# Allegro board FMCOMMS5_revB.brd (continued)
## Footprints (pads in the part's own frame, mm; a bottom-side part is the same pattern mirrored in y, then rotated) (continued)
FL0603
  rect 0.787x0.711 smd: 1(0,-0.555) 3(0,0.555)
  rect 0.66x0.305 smd: 2(-0.955,0) 4(0.955,0)
L0402
  rect 0.699x0.635 smd: 1(-0.54,0) 2(0.54,0)
L0402-2
  rect 0.381x0.66 smd: 1(-0.419,0) 2(0.419,0)
L0805
  rect 1.295x1.473 smd: 1(-0.965,0) 2(0.965,0)
L0805-F
  rect 1.092x1.499 smd: 1(-1.046,0) 2(1.046,0)
L1210H67
  rect 1.245x2.007 smd: 1(-1.272,0) 2(1.272,0)
L7144A
  rect 0.686x1.016 smd: 1(-0.699,0) 2(0.699,0)
LED0603
  rect 0.965x0.762 smd: A(0.8,0) C(-0.8,0)
LSMSQ157H83
  rect 1.473x3.683 smd: 1(-1.232,0) 2(1.232,0)
LSMSQ189H123
  custom 0.435x0.435 smd: 1(-2.103,0) 2(2.103,0)
MSOP8
  rect 0.305x1.321 smd: 1(-0.975,-2.3) 2(-0.325,-2.3) 3(0.325,-2.3) 4(0.975,-2.3) 5(0.975,2.3) 6(0.325,2.3) 7(-0.325,2.3) 8(-0.975,2.3)
QFN8_3X3_PAD1_75X1_45
  oval 0.305x0.813 smd: 1(-0.75,-1.35) 2(-0.25,-1.35) 3(0.25,-1.35) 4(0.75,-1.35) 5(0.75,1.35) 6(0.25,1.35) 7(-0.25,1.35) 8(-0.75,1.35)
  rect 1.753x1.448 smd: PAD(0,0)
QFN8_3X3_PAD2_44X1_7
  oval 0.305x0.914 smd: 1(-0.75,-1.557) 2(-0.25,-1.557) 3(0.25,-1.557) 4(0.75,-1.557) 5(0.75,1.557) 6(0.25,1.557) 7(-0.25,1.557) 8(-0.75,1.557)
  rect 2.438x1.702 smd: PAD(0,0)
QFN16_3X3_PAD1_75X1_75
  oval 0.305x0.94 smd: 1(-0.75,-1.57) 2(-0.25,-1.57) 3(0.25,-1.57) 4(0.75,-1.57) 9(0.75,1.57) 10(0.25,1.57) 11(-0.25,1.57) 12(-0.75,1.57)
  oval 0.94x0.305 smd: 5(1.57,-0.75) 6(1.57,-0.25) 7(1.57,0.25) 8(1.57,0.75) 13(-1.57,0.75) 14(-1.57,0.25) 15(-1.57,-0.25) 16(-1.57,-0.75)
  rect 1.753x1.753 smd: PAD(0,0)
QFN16_4X4_PAD2_1X2_1
  oval 0.356x1.041 smd: 1(-0.975,-1.9) 2(-0.325,-1.9) 3(0.325,-1.9) 4(0.975,-1.9) 9(0.975,1.9) 10(0.325,1.9) 11(-0.325,1.9) 12(-0.975,1.9)
  oval 1.041x0.356 smd: 5(1.9,-0.975) 6(1.9,-0.325) 7(1.9,0.325) 8(1.9,0.975) 13(-1.9,0.975) 14(-1.9,0.325) 15(-1.9,-0.325) 16(-1.9,-0.975)
  rect 2.108x2.108 smd: PAD(0,0)
QFN16_4X4_PAD2_5X2_5
  oval 0.356x0.991 smd: 1(-0.975,-1.974) 2(-0.325,-1.974) 3(0.325,-1.974) 4(0.975,-1.974) 9(0.975,1.974) 10(0.325,1.974) 11(-0.325,1.974) 12(-0.975,1.974)
  oval 0.991x0.356 smd: 5(1.974,-0.975) 6(1.974,-0.325) 7(1.974,0.325) 8(1.974,0.975) 13(-1.974,0.975) 14(-1.974,0.325) 15(-1.974,-0.325) 16(-1.974,-0.975)
  rect 2.489x2.489 smd: PAD(0,0)
QFN20_4X4_PAD2_6X2_6
  oval 0.305x1.041 smd: 1(-1,-2.019) 2(-0.5,-2.019) 3(0,-2.019) 4(0.5,-2.019) 5(1,-2.019) 11(1,2.019) 12(0.5,2.019) 13(0,2.019) 14(-0.5,2.019) 15(-1,2.019)
  oval 1.041x0.305 smd: 6(2.019,-1) 7(2.019,-0.5) 8(2.019,0) 9(2.019,0.5) 10(2.019,1) 16(-2.019,1) 17(-2.019,0.5) 18(-2.019,0) 19(-2.019,-0.5) 20(-2.019,-1)
  rect 2.591x2.591 smd: PAD(0,0)
QFN24_4X4_PAD2_3X2_3
  oval 0.305x0.991 smd: 1(-1.25,-2) 2(-0.75,-2) 3(-0.25,-2) 4(0.25,-2) 5(0.75,-2) 6(1.25,-2) 13(1.25,2) 14(0.75,2) 15(0.25,2) 16(-0.25,2) 17(-0.75,2) 18(-1.25,2)
  oval 0.991x0.305 smd: 7(2,-1.25) 8(2,-0.75) 9(2,-0.25) 10(2,0.25) 11(2,0.75) 12(2,1.25) 19(-2,1.25) 20(-2,0.75) 21(-2,0.25) 22(-2,-0.25) 23(-2,-0.75) 24(-2,-1.25)
  rect 2.311x2.311 smd: PAD(0,0)
QFN32_5X5_PAD3_5X3_5
  oval 0.305x0.889 smd: 1(-1.75,-2.45) 2(-1.25,-2.45) 3(-0.75,-2.45) 4(-0.25,-2.45) 5(0.25,-2.45) 6(0.75,-2.45) 7(1.25,-2.45) 8(1.75,-2.45) 17(1.75,2.45) 18(1.25,2.45) 19(0.75,2.45) 20(0.25,2.45) 21(-0.25,2.45) 22(-0.75,2.45) 23(-1.25,2.45) 24(-1.75,2.45)
  oval 0.889x0.305 smd: 9(2.45,-1.75) 10(2.45,-1.25) 11(2.45,-0.75) 12(2.45,-0.25) 13(2.45,0.25) 14(2.45,0.75) 15(2.45,1.25) 16(2.45,1.75) 25(-2.45,1.75) 26(-2.45,1.25) 27(-2.45,0.75) 28(-2.45,0.25) 29(-2.45,-0.25) 30(-2.45,-0.75) 31(-2.45,-1.25) 32(-2.45,-1.75)
  rect 3.505x3.505 smd: PAD(0,0)
R0201
  rect 0.356x0.356 smd: 1(-0.305,0) 2(0.305,0)
R0402
  rect 0.889x0.813 smd: 1(-0.635,0) 2(0.635,0)
R0603
  rect 0.978x0.889 smd: 1(-0.819,0) 2(0.819,0)
R1206
  rect 1.6x1.6 smd: 1(-1.397,0) 2(1.397,0)
SO8NB-PAD3_1X2_41
  rect 0.635x1.524 smd: 1(-1.905,-2.667) 2(-0.635,-2.667) 3(0.635,-2.667) 4(1.905,-2.667) 5(1.905,2.667) 6(0.635,2.667) 7(-0.635,2.667) 8(-1.905,2.667)
  rect 3.099x2.413 smd: PAD(0,0)
SOT-89
  rect 0.991x1.499 smd: 1(-1.5,-2.224) 3(1.5,-2.224)
  rect 0.991x1.981 smd: 2(0,-1.983)
  rect 2.007x2.997 smd: 4(0,0.728)
TPC75D45
  round 1.905 smd: 1(0,0)
TPSM70X135
  rect 0.356x0.762 smd: 1(0,0)
TSML150W160H160
  rect 0.762x1.651 smd: 1(-1.27,1.587) 2(0,1.587) 3(1.27,1.587) 4(1.27,-1.587) 5(0,-1.587) 6(-1.27,-1.587)
TSSOP8
  rect 0.33x1.651 smd: 1(-0.975,-2.92) 2(-0.325,-2.92) 3(0.325,-2.92) 4(0.975,-2.92) 5(0.975,2.92) 6(0.325,2.92) 7(-0.325,2.92) 8(-0.975,2.92)
unnamed#2
  round 3.175 hole 2.667: 1(0,0)
XFMR2450BL15B050
  rect 0.356x0.991 smd: 1(-0.656,-0.895) 2(0,-0.895) 3(0.656,-0.895) 4(0.656,0.895) 5(0,0.895) 6(-0.656,0.895)
YSML126W98H47
  rect 1.397x1.194 smd: 1(-1.2,-0.95) 2(1.2,-0.95) 3(1.2,0.95) 4(-1.2,0.95)

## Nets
3.3VAUX: C310.1(N1) C311.2(N2) C312.1(N1) P401.D32(N32) P402.D32(N32) R401.2(N2) R402.2(N2) U303.8(VCC) U304.10(VDD) U304.16(VDRIVE) U304.17(PD_N/RST_N)
5V: C540.2(N2) C541.2(N2) C542.2(N2) E507.1(N1) E509.1(N1) R309.1(N1) TP306.1(N1) U502.2(VOUT)
12V: C530.2(N2) C531.2(N2) C532.2(N2) C533.2(N2) P401.C35(N35) P401.C37(N37) P402.C35(N35) P402.C37(N37) P501.3(N3) U501.1(VIN) U501.4(SYNC)
GND_POWER: C103.2(N2) C104.1(N1) C105.2(N2) C112.1(N1) C113.1(N1) C114.1(N1) C115.1(N1) C116.2(N2) C117.2(N2) C118.1(N1) C119.2(N2) C120.1(N1) C121.2(N2) C134.1(N1) C135.2(N2) C143.2(N2) C144.2(N2) C145.2(N2) C146.1(N1) C147.1(N1) C148.2(N2) C149.1(N1) C150.2(N2) C151.1(N1) C152.2(N2) C153.1(N1) C154.1(N1) C155.1(N1) C156.1(N1) C166.1(N1) C203.2(N2) C204.1(N1) C205.2(N2) C212.1(N1) C213.1(N1) C214.1(N1) C215.1(N1) C216.2(N2) C217.2(N2) C218.1(N1) C219.2(N2) C220.1(N1) C221.2(N2) C234.1(N1) C235.2(N2) C243.2(N2) C244.2(N2) C245.2(N2) C246.1(N1) C247.1(N1) C248.2(N2) C249.1(N1) C250.2(N2) C251.1(N1) C252.2(N2) C253.1(N1) C254.1(N1) C255.1(N1) C256.1(N1) C266.1(N1) C302.2(N2) C303.2(N2) C304.2(N2) C305.2(N2) C306.2(N2) C307.2(N2) C308.2(N2) C309.1(N1) C310.2(N2) C311.1(N1) C312.2(N2) C313.2(N2) C314.2(N2) C317.1(N1) C320.1(N1) C321.1(N1) C322.1(N1) C323.1(N1) C324.1(N1) C325.1(N1) C326.1(N1) C327.1(N1) C328.1(N1) C330.1(N1) C333.2(N2) C334.2(N2) C335.2(N2) C340.2(N2) C341.2(N2) C342.2(N2) C343.2(N2) C344.2(N2) C345.2(N2) C346.2(N2) C347.2(N2) C348.1(N1) C501.2(N2) C502.2(N2) C503.2(N2) C504.2(N2) C505.2(N2) C510.2(N2) C511.2(N2) C512.2(N2) C513.2(N2) C514.2(N2) C515.2(N2) C516.2(N2) C517.2(N2) C518.2(N2) C519.2(N2) C520.2(N2) C521.2(N2) C522.2(N2) C523.2(N2) C524.2(N2) C525.2(N2) C530.1(N1) C531.1(N1) C532.1(N1) C533.1(N1) C534.1(N1) C535.1(N1) C536.1(N1) C537.2(N2) C538.1(N1) C539.1(N1) C540.1(N1) C541.1(N1) C542.1(N1) C543.1(N1) C544.1(N1) C545.2(N2) C546.2(N2) C547.1(N1) C548.1(N1) C549.2(N2) C550.1(N1) C551.2(N2) C552.2(N2) C553.1(N1) C554.1(N1) C555.2(N2) C556.2(N2) C557.2(N2) C558.2(N2) C559.2(N2) C560.2(N2) C561.2(N2) C562.2(N2) C563.2(N2) C564.2(N2) C565.2(N2) C566.2(N2) C567.2(N2) C568.2(N2) C569.2(N2) C570.2(N2) C571.2(N2) C572.2(N2) C573.2(N2) C574.2(N2) C575.2(N2) C576.2(N2) C577.2(N2) C578.2(N2) C579.2(N2) C580.2(N2) C581.2(N2) C582.2(N2) C583.2(N2) C584.2(N2) C585.2(N2) C586.2(N2) C587.2(N2) C588.2(N2) C589.2(N2) C590.2(N2) C591.2(N2) C592.2(N2) C593.2(N2) C594.2(N2) C595.2(N2) C596.2(N2) C597.2(N2) C598.2(N2) C599.2(N2) C607.2(N2) C608.2(N2) C609.2(N2) C610.2(N2) C611.2(N2) C612.2(N2) C613.2(N2) C614.2(N2) C615.2(N2) C616.2(N2) C617.2(N2) C618.2(N2) C619.2(N2) C620.2(N2) C621.2(N2) C622.2(N2) C623.2(N2) C624.2(N2) C625.2(N2) C626.2(N2) C627.2(N2) C628.2(N2) C629.2(N2) C630.2(N2) C631.2(N2) C632.2(N2) C633.2(N2) C634.2(N2) C635.2(N2) C636.2(N2) C637.2(N2) C638.2(N2) C639.2(N2) C640.2(N2) C641.2(N2) C642.2(N2) C643.1(N1) C644.1(N1) C645.1(N1) C646.1(N1) C647.1(N1) C648.1(N1) C649.1(N1) C650.2(N2) C651.1(N1) C688.1(N1) DS301.C(N) FL100.1(GND1) FL100.3(GND2) FL101.1(GND1) FL101.3(GND2) FL102.1(GND1) FL102.3(GND2) FL103.1(GND1) FL103.3(GND2) FL200.1(GND1) FL200.3(GND2) FL201.1(GND1) FL201.3(GND2) FL202.1(GND1) FL202.3(GND2) FL203.1(GND1) FL203.3(GND2) J101.2(SH1) J101.3(SH2) J101.4(SH3) J101.5(SH4) J102.2(SH1) J102.3(SH2) J102.4(SH3) J102.5(SH4) J103.2(SH1) J103.3(SH2) J103.4(SH3) J103.5(SH4) J104.2(SH1) J104.3(SH2) J104.4(SH3) J104.5(SH4) J110.2(SH1) J110.3(SH2) J110.4(SH3) J110.5(SH4) J111.2(SH1) J111.3(SH2) J111.4(SH3) J111.5(SH4) J112.2(SH1) J112.3(SH2) J112.4(SH3) J112.5(SH4) J113.2(SH1) J113.3(SH2) J113.4(SH3) J113.5(SH4) J201.2(SH1) J201.3(SH2) J201.4(SH3) J201.5(SH4) J202.2(SH1) J202.3(SH2) J202.4(SH3) J202.5(SH4) J203.2(SH1) J203.3(SH2) J203.4(SH3) J203.5(SH4) J204.2(SH1) J204.3(SH2) J204.4(SH3) J204.5(SH4) J210.2(SH1) J210.3(SH2) J210.4(SH3) J210.5(SH4) J211.2(SH1) J211.3(SH2) J211.4(SH3) J211.5(SH4) J212.2(SH1) J212.3(SH2) J212.4(SH3) J212.5(SH4) J213.2(SH1) J213.3(SH2) J213.4(SH3) J213.5(SH4) J301.2(SH1) J301.3(SH2) J301.4(SH3) J301.5(SH4) J302.2(SH1) J302.3(SH2) J302.4(SH3) J302.5(SH4) P101.26(N26) P201.26(N26) P401.C1(N1) P401.C4(N4) P401.C5(N5) P401.C8(N8) P401.C9(N9) P401.C12(N12) P401.C13(N13) P401.C16(N16) P401.C17(N17) P401.C20(N20) P401.C21(N21) P401.C24(N24) P401.C25(N25) P401.C28(N28) P401.C29(N29) P401.C32(N32) P401.C33(N33) P401.C36(N36) P401.C38(N38) P401.C40(N40) P401.D2(N2) P401.D3(N3) P401.D6(N6) P401.D7(N7) P401.D10(N10) P401.D13(N13) P401.D16(N16) P401.D19(N19) P401.D22(N22) P401.D25(N25) P401.D28(N28) P401.D37(N37) P401.D39(N39) P401.G1(N1) P401.G4(N4) P401.G5(N5) P401.G8(N8) P401.G11(N11) P401.G14(N14) P401.G17(N17) P401.G20(N20) P401.G23(N23) P401.G26(N26) P401.G29(N29) P401.G32(N32) P401.G35(N35) P401.G38(N38) P401.G40(N40) P401.H2(N2) P401.H3(N3) P401.H6(N6) P401.H9(N9) P401.H12(N12) P401.H15(N15) P401.H18(N18) P401.H21(N21) P401.H24(N24) P401.H27(N27) P401.H30(N30) P401.H33(N33) P401.H36(N36) P401.H39(N39) P402.C1(N1) P402.C4(N4) P402.C5(N5) P402.C8(N8) P402.C9(N9) P402.C12(N12) P402.C13(N13) P402.C16(N16) P402.C17(N17) P402.C20(N20) P402.C21(N21) P402.C24(N24) P402.C25(N25) P402.C28(N28) P402.C29(N29) P402.C32(N32) P402.C33(N33) P402.C36(N36) P402.C38(N38) P402.C40(N40) P402.D2(N2) P402.D3(N3) P402.D6(N6) P402.D7(N7) P402.D10(N10) P402.D13(N13) P402.D16(N16) P402.D19(N19) P402.D22(N22) P402.D25(N25) P402.D28(N28) P402.D37(N37) P402.D39(N39) P402.G1(N1) P402.G4(N4) P402.G5(N5) P402.G8(N8) P402.G11(N11) P402.G14(N14) P402.G17(N17) P402.G20(N20) P402.G23(N23) P402.G26(N26) P402.G29(N29) P402.G32(N32) P402.G35(N35) P402.G38(N38) P402.G40(N40) P402.H2(N2) P402.H3(N3) P402.H6(N6) P402.H9(N9) P402.H12(N12) P402.H15(N15) P402.H18(N18) P402.H21(N21) P402.H24(N24) P402.H27(N27) P402.H30(N30) P402.H33(N33) P402.H36(N36) P402.H39(N39) P501.2(N2) R101.1(N1) R102.1(N1) R104.2(N2) R105.2(N2) R106.2(N2) R107.2(N2) R111.1(N1) R125.2(N2) R201.1(N1) R202.1(N1) R204.2(N2) R205.2(N2) R206.2(N2) R207.2(N2) R211.1(N1) R225.2(N2) R301.1(N1) R306.1(N1) R307.1(N1) R308.1(N1) R312.1(N1) R313.1(N1) R314.1(N1) R315.1(N1) R319.2(N2) R320.2(N2) R323.1(N1) R328.1(N1) R329.1(N1) R335.1(N1) R350.1(N1) R351.2(N2) R406.2(N2) R501.1(N1) R505.1(N1) R509.1(N1) R513.1(N1) R517.1(N1) R521.2(N2) T101.2(GND_DC_FEED_RFGND) T101.5(GND) T102.2(GND_DC_FEED_RFGND) T102.5(GND) T103.1(NC1) T103.2(PRI) T103.5(NC2) T104.1(NC1) T104.2(PRI) T104.5(NC2) T105.1(NC1) T105.2(PRI) T105.5(NC2) T106.1(NC1) T106.2(PRI) T106.5(NC2) T107.1(NC1) T107.2(PRI) T107.5(NC2) T108.1(NC1) T108.2(PRI) T108.5(NC2) T201.2(GND_DC_FEED_RFGND) T201.5(GND) T202.2(GND_DC_FEED_RFGND) T202.5(GND) T203.1(NC1) T203.2(PRI) T203.5(NC2) T204.1(NC1) T204.2(PRI) T204.5(NC2) T205.1(NC1) T205.2(PRI) T205.5(NC2) T206.1(NC1) T206.2(PRI) T206.5(NC2) T207.1(NC1) T207.2(PRI) T207.5(NC2) T208.1(NC1) T208.2(PRI) T208.5(NC2) U101.A4(VSSA26) U101.A6(VSSA01) U101.B1(VSSA02) U101.B2(VSSA03) U101.B12(VSSA04) U101.C1(RX2C_P) U101.C2(VSSA05) U101.C4(TEST/ENABLE) U101.C7(VSSA06) U101.C8(VSSA07) U101.C9(VSSA08) U101.C10(VSSA09) U101.C11(VSSA10) U101.C12(VSSA11) U101.D1(RX2C_N) U101.D12(VSSD01) U101.F3(VSSA12) U101.F7(VSSD02) U101.F9(VSSD03) U101.F11(VSSD04) U101.G12(VSSD05) U101.H2(VSSA13) U101.H3(VSSA14) U101.H6(VSSA28) U101.H7(VSSD06) U101.H10(VSSD07) U101.J2(VSSA15) U101.K2(VSSA16) U101.K12(VSSD08) U101.L2(VSSA17) U101.L3(VSSA18) U101.L7(VSSA19) U101.L8(VSSA20) U101.L9(VSSA21) U101.L10(VSSA22) U101.L11(VSSA23) U101.L12(VSSA24) U101.M4(VSSA27) U101.M6(VSSA25) U102.PAD U103.PAD U104.2(GND) U104.4(GND1) U105.2(GND) U105.4(GND1) U201.A4(VSSA26) U201.A6(VSSA01) U201.B1(VSSA02) U201.B2(VSSA03) U201.B12(VSSA04) U201.C1(RX2C_P) U201.C2(VSSA05) U201.C4(TEST/ENABLE) U201.C7(VSSA06) U201.C8(VSSA07) U201.C9(VSSA08) U201.C10(VSSA09) U201.C11(VSSA10) U201.C12(VSSA11) U201.D1(RX2C_N) U201.D12(VSSD01) U201.F3(VSSA12) U201.F7(VSSD02) U201.F9(VSSD03) U201.F11(VSSD04) U201.G12(VSSD05) U201.H2(VSSA13) U201.H3(VSSA14) U201.H6(VSSA28) U201.H7(VSSD06) U201.H10(VSSD07) U201.J2(VSSA15) U201.K2(VSSA16) U201.K12(VSSD08) U201.L2(VSSA17) U201.L3(VSSA18) U201.L7(VSSA19) U201.L8(VSSA20) U201.L9(VSSA21) U201.L10(VSSA22) U201.L11(VSSA23) U201.L12(VSSA24) U201.M4(VSSA27) U201.M6(VSSA25) U202.PAD U203.PAD U204.2(GND) U204.4(GND1) U205.2(GND) U205.4(GND1) U301.6(CTRL_B) U301.7(SLEEP) U301.PAD U302.8(CPGND) U302.9(AGND) U302.13(AGNDRF1) U302.15(AGNDRF2) U302.18(AGNDVCO1) U302.21(AGNDVCO2) U302.31(SDGND) U302.PAD U303.3(E2) U303.4(VSS) U303.7(WC_N) U304.6(GND1) U304.9(GND) U304.PAD U305.3(GND1) U305.6(GND2) U305.7(GND3) U306.3(GND1) U306.6(GND2) U306.7(GND3) U307.1(GND1) U307.4(GND2) U307.5(GND3) U307.8(GND4) U307.9(GND5) U307.12(GND6) U307.14(GND7) U307.PAD U501.2(FSEL) U501.8(PGND) U501.PAD(EPAD) U502.4(GND) U502.PAD(EP) U503.2(RT) U503.5(GND) U503.6(PGND_1) U503.7(PGND_2) U503.8(PGND_3) U503.PAD U504.6(GND) U504.PAD U505.6(GND) U505.PAD U506.6(GND) U506.PAD U507.6(GND) U507.PAD U508.4(GND) U508.PAD(EP) Y301.2(GND)
VDD_AMP_5V: C103.1(N1) C112.2(N2) C113.2(N2) C152.1(N1) C153.2(N2) C154.2(N2) C203.1(N1) C212.2(N2) C213.2(N2) C252.1(N1) C253.2(N2) C254.2(N2) C547.2(N2) C548.2(N2) E509.2(N2) L110.2(N2) L111.2(N2) L210.2(N2) L211.2(N2)
VDD_EXT_LO_3P3: C306.1(N1) C307.1(N1) C308.1(N1) C333.1(N1) C334.1(N1) C335.1(N1) C648.2(N2) C649.2(N2) C651.2(N2) C688.2(N2) R303.1(N1) R317.2(N2) R318.2(N2) U302.4(CE) U302.10(VRF) U302.16(AVDD_2) U302.27(DVDD) U307.13(VCC1) U307.15(VCC2) U307.16(VCC3) U508.2(VOUT)
VDD_INTERFACE_A: C610.1(N1) C611.1(N1) C612.1(N1) C613.1(N1) E512.2(N2) R103.1(N1) R403.1(N1) R407.1(N1) R507.2(N2) R511.2(N2) U101.H12(VDD_INTERFACE)
VDD_INTERFACE_B: C614.1(N1) C615.1(N1) C616.1(N1) C617.1(N1) E514.2(N2) R203.1(N1) R405.1(N1) R515.2(N2) R519.2(N2) U201.H12(VDD_INTERFACE)
VDD_LNA_3P3: C148.1(N1) C150.1(N1) C248.1(N1) C250.1(N1) C510.1(N1) C511.1(N1) C512.1(N1) C513.1(N1) E504.1(N1) R109.2(N2) R112.2(N2) R209.2(N2) R212.2(N2)
VDD_RF_SW: C340.1(N1) C341.1(N1) C342.1(N1) C343.1(N1) C344.1(N1) C345.1(N1) C638.1(N1) C639.1(N1) C640.1(N1) C641.1(N1) E1.2(N2) U305.1(VDD) U306.1(VDD)
VDD_VCO_5V: C309.2(N2) C317.2(N2) C320.2(N2) C323.2(N2) C543.2(N2) C544.2(N2) E507.2(N2) U302.6(VP) U302.17(VVCO) U302.19(VREGVCO)
VDDA_GPO_A: C518.1(N1) C519.1(N1) C520.1(N1) C521.1(N1) E501.2(N2) U101.B8(VDDA_GPO)
VDDA_GPO_B: C522.1(N1) C523.1(N1) C524.1(N1) C525.1(N1) E503.2(N2) U201.B8(VDDA_GPO)
1P3_DIG_A: C118.2(N2) C119.1(N1) C120.2(N2) C121.1(N1) C134.2(N2) C135.1(N1) C584.1(N1) C585.1(N1) C586.1(N1) C587.1(N1) C588.1(N1) C589.1(N1) C590.1(N1) C591.1(N1) C592.1(N1) C593.1(N1) L101.1(N1) L102.1(N1) L103.1(N1) L104.1(N1) L105.1(N1) L107.1(N1) R325.1(N1) R514.2(N2) U101.D2(VDDA1P3_RX_RF) U101.D3(VDDA1P3_RX_TX) U101.E3(VDDA1P3_TX_LO_BUFFER) U101.F12(VDDD1P3_DIG) U101.K4(VDDA1P3_BB)
1P3_DIG_B: C218.2(N2) C219.1(N1) C220.2(N2) C221.1(N1) C234.2(N2) C235.1(N1) C628.1(N1) C629.1(N1) C630.1(N1) C631.1(N1) C632.1(N1) C633.1(N1) C634.1(N1) C635.1(N1) C636.1(N1) C637.1(N1) L201.1(N1) L202.1(N1) L203.1(N1) L204.1(N1) L205.1(N1) L207.1(N1) R327.1(N1) R522.1(N1) U201.D2(VDDA1P3_RX_RF) U201.D3(VDDA1P3_RX_TX) U201.E3(VDDA1P3_TX_LO_BUFFER) U201.F12(VDDD1P3_DIG) U201.K4(VDDA1P3_BB)
1P3_RF_A: C568.1(N1) C569.1(N1) C570.1(N1) C571.1(N1) C572.1(N1) C573.1(N1) C574.1(N1) C575.1(N1) R326.1(N1) R510.2(N2) U101.B9(VDDA1P3_TX_LO) U101.B10(VDDA1P3_TX_VCO_LDO) U101.E2(VDDA1P3_RX_LO) U101.F2(VDDA1P3_RX_VCO_LDO) U101.J3(VDDA1P3_RX_SYNTH) U101.K3(VDDA1P3_TX_SYNTH)
1P3_RF_B: C515.1(N1) C516.1(N1) C517.1(N1) C545.1(N1) C546.1(N1) C607.1(N1) C608.1(N1) C609.1(N1) R310.1(N1) R518.2(N2) TP307.1(N1) U201.B9(VDDA1P3_TX_LO) U201.B10(VDDA1P3_TX_VCO_LDO) U201.E2(VDDA1P3_RX_LO) U201.F2(VDDA1P3_RX_VCO_LDO) U201.J3(VDDA1P3_RX_SYNTH) U201.K3(VDDA1P3_TX_SYNTH)
1P3_TX2A_A: U101.A9(TX2B_N) U101.A10(TX2B_P)
1P3_TX2A_B: U201.A9(TX2B_N) U201.A10(TX2B_P)
1P8_CLK: C303.1(N1) C304.1(N1) C305.1(N1) C346.1(N1) C347.1(N1) C557.1(N1) C558.1(N1) C559.1(N1) E511.2(N2) U301.4(VS1) U301.5(CTRL_A) U301.10(VS2) U301.13(VS3) U301.16(VS4) U301.19(VS5) U301.22(VS6) Y301.1(E/D) Y301.4(VDD)
1P8V: C553.2(N2) C554.2(N2) C555.1(N1) C556.1(N1) C560.1(N1) C576.1(N1) C594.1(N1) C620.1(N1) E510.2(N2) E511.1(N1) E513.1(N1) R302.2(N2) R305.1(N1) R506.2(N2) TP303.1(N1) U504.1(VIN1) U504.2(VIN2) U504.3(VIN3) U504.15(VIN4) U504.16(VIN5) U505.1(VIN1) U505.2(VIN2) U505.3(VIN3) U505.15(VIN4) U505.16(VIN5) U506.1(VIN1) U506.2(VIN2) U506.3(VIN3) U506.15(VIN4) U506.16(VIN5) U507.1(VIN1) U507.2(VIN2) U507.3(VIN3) U507.15(VIN4) U507.16(VIN5)
3P3V: C501.1(N1) C502.1(N1) L501.1(N1) P401.C39(N39) P401.D36(N36) P401.D38(N38) P401.D40(N40) P402.C39(N39) P402.D36(N36) P402.D38(N38) P402.D40(N40) P501.1(N1) R304.1(N1) TP302.1(N1)
5355_LE: P401.H34(N34) R407.2(N2) U302.3(LE)
5355_LOCK: P401.H37(N37) R351.1(N1) U302.30(MUXOUT)
5355_REF_N: C319.2(N2) U302.29(REFINA)
5355_REF_P: C318.2(N2) U302.28(REFINB)
5355_RF_EN: P401.H31(N31) U302.26(PDBRF)
5355_RFOUT_N: C332.1(N1) R318.1(N1) U302.12(RFOUTA-)
5355_RFOUT_P: C331.1(N1) R317.1(N1) U302.11(RFOUTA+)
13617_IN_N: C332.2(N2) C390.1(N1) U307.6(DINP)
13617_IN_P: C331.2(N2) R350.2(N2) U307.7(DINN)
AUXADC_A: C143.1(N1) P101.21(N21) U101.L5(AUXADC)
AUXADC_B: C243.1(N1) P201.21(N21) U201.L5(AUXADC)
AUXDAC1_A: C144.1(N1) P101.22(N22) U101.B3(AUXDAC1)
AUXDAC1_B: C244.1(N1) P201.22(N22) U201.B3(AUXDAC1)
AUXDAC2_A: C145.1(N1) P101.23(N23) U101.C3(AUXDAC2)
AUXDAC2_B: C245.1(N1) P201.23(N23) U201.C3(AUXDAC2)
CAL_SW_1: CAL_SW_1.1(N1) P401.D26(N26) R319.1(N1) U305.2(CTRL)
CAL_SW_2: CAL_SW_2.1(N1) P401.D27(N27) R320.1(N1) U306.2(CTRL)
CAL_SW_3: CAL_SW_3.1(N1) P402.D26(N26)
CAL_SW_4: CAL_SW_4.1(N1) P402.D27(N27)
CLK_OUT_A: C142.1(N1) U101.J6(CLK_OUT)
CLK_OUT_B: C242.1(N1) U201.J6(CLK_OUT)
CTRL_IN0_A: P101.20(N20) P401.D23(N23) R107.1(N1) U101.C5(CTRL_IN0)
CTRL_IN0_B: P201.20(N20) P402.D23(N23) R207.1(N1) U201.C5(CTRL_IN0)
CTRL_IN1_A: P101.19(N19) P401.D24(N24) R106.1(N1) U101.C6(CTRL_IN1)
CTRL_IN1_B: P201.19(N19) P402.D24(N24) R206.1(N1) U201.C6(CTRL_IN1)
CTRL_IN2_A: P101.18(N18) P401.H28(N28) R105.1(N1) U101.D6(CTRL_IN2)
CTRL_IN2_B: P201.18(N18) P402.H28(N28) R205.1(N1) U201.D6(CTRL_IN2)
CTRL_IN3_A: P101.17(N17) P401.H29(N29) R104.1(N1) U101.D5(CTRL_IN3)
CTRL_IN3_B: P201.17(N17) P402.H29(N29) R204.1(N1) U201.D5(CTRL_IN3)
CTRL_OUT0_A: P101.11(N11) P401.H22(N22) U101.D4(CTRL_OUT0)
CTRL_OUT0_B: P201.11(N11) P402.H22(N22) U201.D4(CTRL_OUT0)
CTRL_OUT1_A: P101.10(N10) P401.H23(N23) U101.E4(CTRL_OUT1)
CTRL_OUT1_B: P201.10(N10) P402.H23(N23) U201.E4(CTRL_OUT1)
CTRL_OUT2_A: P101.9(N9) P401.G21(N21) U101.E5(CTRL_OUT2)
CTRL_OUT2_B: P201.9(N9) P402.G21(N21) U201.E5(CTRL_OUT2)
CTRL_OUT3_A: P101.8(N8) P401.G22(N22) U101.E6(CTRL_OUT3)
CTRL_OUT3_B: P201.8(N8) P402.G22(N22) U201.E6(CTRL_OUT3)
CTRL_OUT4_A: P101.7(N7) P401.H25(N25) U101.F6(CTRL_OUT4)
CTRL_OUT4_B: P201.7(N7) P402.H25(N25) U201.F6(CTRL_OUT4)
CTRL_OUT5_A: P101.6(N6) P401.H26(N26) U101.F5(CTRL_OUT5)
CTRL_OUT5_B: P201.6(N6) P402.H26(N26) U201.F5(CTRL_OUT5)
CTRL_OUT6_A: P101.5(N5) P401.G24(N24) U101.F4(CTRL_OUT6)
CTRL_OUT6_B: P201.5(N5) P402.G24(N24) U201.F4(CTRL_OUT6)
CTRL_OUT7_A: P101.4(N4) P401.G25(N25) U101.G4(CTRL_OUT7)
CTRL_OUT7_B: P201.4(N4) P402.G25(N25) U201.G4(CTRL_OUT7)
DATA_CLK_N_A: DATA_CLK_N_A.1(N1) P401.G7(N7) U101.H11(DATA_CLK_N)
DATA_CLK_N_B: DATA_CLK_N_B.1(N1) P402.G7(N7) U201.H11(DATA_CLK_N)
DATA_CLK_P_A: DATA_CLK_P_A.1(N1) P401.G6(N6) U101.G11(DATA_CLK_P)
DATA_CLK_P_B: DATA_CLK_P_B.1(N1) P402.G6(N6) U201.G11(DATA_CLK_P)
DEBUG_1: DEBUG_1.1(N1) P401.C26(N26)
DEBUG_2: DEBUG_2.1(N1) P401.C27(N27)
DEBUG_3: DEBUG_3.1(N1) P402.C26(N26)
DEBUG_4: DEBUG_4.1(N1) P402.C27(N27)
EN_AGC_A: P101.3(N3) P401.G27(N27) U101.G5(EN_AGC)
EN_AGC_B: P201.3(N3) P402.G27(N27) U201.G5(EN_AGC)
ENABLE_A: P101.1(N1) P401.G18(N18) U101.G6(ENABLE)
ENABLE_B: P201.1(N1) P402.G18(N18) U201.G6(ENABLE)
FB_CLK_N_A: FB_CLK_N_A.1(N1) P401.G13(N13) U101.G10(FB_CLK_N)
FB_CLK_N_B: FB_CLK_N_B.1(N1) P402.G13(N13) U201.G10(FB_CLK_N)
FB_CLK_P_A: FB_CLK_P_A.1(N1) P401.G12(N12) U101.F10(FB_CLK_P)
FB_CLK_P_B: FB_CLK_P_B.1(N1) P402.G12(N12) U201.F10(FB_CLK_P)
GA0: P401.C34(N34) U303.2(E1) U304.11(AS0)
GA1: P401.D35(N35) U303.1(E0) U304.13(AS1)
GPO0_A: P101.12(N12) U101.B7(GPO_0)
GPO0_B: P201.12(N12) U201.B7(GPO_0)
GPO1_A: P101.13(N13) U101.B6(GPO_1)
GPO1_B: P201.13(N13) U201.B6(GPO_1)
GPO2_A: P101.14(N14) U101.B5(GPO_2)
GPO2_B: P201.14(N14) U201.B5(GPO_2)
GPO3_A: P101.15(N15) U101.B4(GPO_3)
GPO3_B: P201.15(N15) U201.B4(GPO_3)
PG_1P3_DIG_A: R511.1(N1) U505.5(PG)
PG_1P3_DIG_B: R519.1(N1) U507.5(PG)
PG_1P3_RF_A: R507.1(N1) U504.5(PG)
PG_1P3_RF_B: R515.1(N1) U506.5(PG)
PG_1P8V: R504.1(N1) U503.16(PGOOD) U504.4(EN) U505.4(EN) U506.4(EN) U507.4(EN)
PG_5V: U501.6(PG)
PG_FMC: P401.D1(N1) U501.3(EN) U503.15(EN)
REF_CLK_FMC_N: P401.D21(N21) REF_CLK_FMC_N.1(N1) U301.14(OUT3_N)
REF_CLK_FMC_P: P401.D20(N20) REF_CLK_FMC_P.1(N1) U301.15(OUT3)
RESET_A: P101.25(N25) P401.C23(N23) R103.2(N2) U101.K5(RESETB)
RESET_B: P201.25(N25) P402.G30(N30) R203.2(N2) U201.K5(RESETB)
RX1A_A: J111.1(CNTR) T106.3(PRI_DOT)
RX1A_B: J210.1(CNTR) T205.3(PRI_DOT)
RX1A_N_A: C106.2(N2) U101.M2(RX1A_N)
RX1A_N_B: C208.2(N2) U201.M2(RX1A_N)
RX1A_P_A: C107.2(N2) U101.M1(RX1A_P)
RX1A_P_B: C209.2(N2) U201.M1(RX1A_P)
RX1B_A: C146.2(N2) J103.1(CNTR) L106.1(N1)
RX1B_B: C246.2(N2) J203.1(CNTR) L206.1(N1)
RX1B_N_A: C128.2(N2) U101.J1(RX1B_N)
RX1B_N_B: C228.2(N2) U201.J1(RX1B_N)
RX1B_P_A: C129.2(N2) U101.H1(RX1B_P)
RX1B_P_B: C229.2(N2) U201.H1(RX1B_P)
RX1C_A: C351.2(N2) T103.3(PRI_DOT)
RX1C_B: C352.2(N2) T203.3(PRI_DOT)
RX1C_N_A: C126.2(N2) U101.L1(RX1C_N)
RX1C_N_B: C226.2(N2) U201.L1(RX1C_N)
RX1C_P_A: C127.2(N2) U101.K1(RX1C_P)
RX1C_P_B: C227.2(N2) U201.K1(RX1C_P)
RX2A_A: J110.1(CNTR) T105.3(PRI_DOT)
RX2A_B: J211.1(CNTR) T206.3(PRI_DOT)
RX2A_N_A: C108.2(N2) U101.A1(RX2A_N)
RX2A_N_B: C206.2(N2) U201.A1(RX2A_N)
RX2A_P_A: C109.2(N2) U101.A2(RX2A_P)
RX2A_P_B: C207.2(N2) U201.A2(RX2A_P)
RX2B_A: C151.2(N2) J104.1(CNTR) L108.1(N1)
RX2B_B: C251.2(N2) J204.1(CNTR) L208.1(N1)
RX2B_N_A: C130.2(N2) U101.F1(RX2B_N)
RX2B_N_B: C230.2(N2) U201.F1(RX2B_N)
RX2B_P_A: C131.2(N2) U101.E1(RX2B_P)
RX2B_P_B: C231.2(N2) U201.E1(RX2B_P)
RX_D0_N_A: P401.H8(N8) RX_D0_N_A.1(N1) U101.K11(P1_D0/RX_D0_N)
RX_D0_N_B: P402.H8(N8) RX_D0_N_B.1(N1) U201.K11(P1_D0/RX_D0_N)
RX_D0_P_A: P401.H7(N7) RX_D0_P_A.1(N1) U101.J12(P1_D1/RX_D0_P)
RX_D0_P_B: P402.H7(N7) RX_D0_P_B.1(N1) U201.J12(P1_D1/RX_D0_P)
RX_D1_N_A: P401.G10(N10) RX_D1_N_A.1(N1) U101.K10(P1_D2/RX_D1_N)
RX_D1_N_B: P402.G10(N10) RX_D1_N_B.1(N1) U201.K10(P1_D2/RX_D1_N)
RX_D1_P_A: P401.G9(N9) RX_D1_P_A.1(N1) U101.J11(P1_D3/RX_D1_P)
RX_D1_P_B: P402.G9(N9) RX_D1_P_B.1(N1) U201.J11(P1_D3/RX_D1_P)
RX_D2_N_A: P401.H11(N11) RX_D2_N_A.1(N1) U101.K9(P1_D4/RX_D2_N)
RX_D2_N_B: P402.H11(N11) RX_D2_N_B.1(N1) U201.K9(P1_D4/RX_D2_N)
RX_D2_P_A: P401.H10(N10) RX_D2_P_A.1(N1) U101.J10(P1_D5/RX_D2_P)
RX_D2_P_B: P402.H10(N10) RX_D2_P_B.1(N1) U201.J10(P1_D5/RX_D2_P)
RX_D3_N_A: P401.D12(N12) RX_D3_N_A.1(N1) U101.K8(P1_D6/RX_D3_N)
RX_D3_N_B: P402.D12(N12) RX_D3_N_B.1(N1) U201.K8(P1_D6/RX_D3_N)
RX_D3_P_A: P401.D11(N11) RX_D3_P_A.1(N1) U101.J9(P1_D7/RX_D3_P)
RX_D3_P_B: P402.D11(N11) RX_D3_P_B.1(N1) U201.J9(P1_D7/RX_D3_P)
RX_D4_N_A: P401.C11(N11) RX_D4_N_A.1(N1) U101.K7(P1_D8/RX_D4_N)
RX_D4_N_B: P402.C11(N11) RX_D4_N_B.1(N1) U201.K7(P1_D8/RX_D4_N)
RX_D4_P_A: P401.C10(N10) RX_D4_P_A.1(N1) U101.J8(P1_D9/RX_D4_P)
RX_D4_P_B: P402.C10(N10) RX_D4_P_B.1(N1) U201.J8(P1_D9/RX_D4_P)
RX_D5_N_A: P401.H14(N14) RX_D5_N_A.1(N1) U101.J7(P1_D10/RX_D5_N)
RX_D5_N_B: P402.H14(N14) RX_D5_N_B.1(N1) U201.J7(P1_D10/RX_D5_N)
RX_D5_P_A: P401.H13(N13) RX_D5_P_A.1(N1) U101.H8(P1_D11/RX_D5_P)
RX_D5_P_B: P402.H13(N13) RX_D5_P_B.1(N1) U201.H8(P1_D11/RX_D5_P)
RX_EXT_LO_A: C336.2(N2) U101.G1(RX_EXT_LO_IN)
RX_EXT_LO_B: C338.2(N2) U201.G1(RX_EXT_LO_IN)
RX_FRAME_N_A: P401.D9(N9) RX_FRAME_N_A.1(N1) U101.G7(RX_FRAME_N)
RX_FRAME_N_B: P402.D9(N9) RX_FRAME_N_B.1(N1) U201.G7(RX_FRAME_N)
RX_FRAME_P_A: P401.D8(N8) RX_FRAME_P_A.1(N1) U101.G8(RX_FRAME_P)
RX_FRAME_P_B: P402.D8(N8) RX_FRAME_P_B.1(N1) U201.G8(RX_FRAME_P)
SCL: P401.C30(N30) R401.1(N1) U303.6(SCL) U304.15(SCL)
SDA: P401.C31(N31) R402.1(N1) U303.5(SDA) U304.14(SDA)
SPI_CLK: R404.2(N2) R406.1(N1) SPI_CLK.1(N1) U101.J5(SPI_CLK) U201.J5(SPI_CLK) U302.1(CLK)
SPI_DI: P401.G33(N33) SPI_DI.1(N1) U101.J4(SPI_DI) U201.J4(SPI_DI) U302.2(DATA)
SPI_DO: P401.G34(N34) SPI_DO.1(N1) U101.L6(SPI_DO) U201.L6(SPI_DO)
SPI_ENB_A: P401.G30(N30) R403.2(N2) SPI_ENB_A.1(N1) U101.K6(SPI_ENB)
SPI_ENB_B: P401.G31(N31) R405.2(N2) SPI_ENB_B.1(N1) U201.K6(SPI_ENB)
SYNC_IN: P101.24(N24) P201.24(N24) P401.C22(N22) R111.2(N2) R211.2(N2) U101.H5(SYNC_IN) U201.H5(SYNC_IN)
TX1A_A: C137.2(N2) C139.1(N1) J112.1(CNTR)
TX1A_B: C237.2(N2) C239.1(N1) J212.1(CNTR)
TX1A_N_A: C122.1(N1) L101.2(N2) U101.M8(TX1A_N)
TX1A_N_B: C222.1(N1) L201.2(N2) U201.M8(TX1A_N)
TX1A_P_A: C123.1(N1) L103.2(N2) U101.M7(TX1A_P)
TX1A_P_B: C223.1(N1) L203.2(N2) U201.M7(TX1A_P)
TX1B_A: C349.1(N1) T104.3(PRI_DOT)
TX1B_B: C350.1(N1) T204.3(PRI_DOT)
TX1B_N_A: C133.1(N1) L102.2(N2) U101.M10(TX1B_N)
TX1B_N_B: C233.1(N1) L202.2(N2) U201.M10(TX1B_N)
TX1B_P_A: C132.1(N1) L104.2(N2) U101.M9(TX1B_P)
TX1B_P_B: C232.1(N1) L204.2(N2) U201.M9(TX1B_P)
TX2A_A: C111.2(N2) C162.1(N1) J113.1(CNTR)
TX2A_B: C211.2(N2) C262.1(N1) J213.1(CNTR)
TX2A_N_A: C124.1(N1) L105.2(N2) U101.A7(TX2A_N)
TX2A_N_B: C224.1(N1) L205.2(N2) U201.A7(TX2A_N)
TX2A_P_A: C125.1(N1) L107.2(N2) U101.A8(TX2A_P)
TX2A_P_B: C225.1(N1) L207.2(N2) U201.A8(TX2A_P)
TX_D0_N_A: P401.C15(N15) TX_D0_N_A.1(N1) U101.E12(P0_D0/TX_D0_N)
TX_D0_N_B: P402.C15(N15) TX_D0_N_B.1(N1) U201.E12(P0_D0/TX_D0_N)
TX_D0_P_A: P401.C14(N14) TX_D0_P_A.1(N1) U101.D11(P0_D1/TX_D0_P)
TX_D0_P_B: P402.C14(N14) TX_D0_P_B.1(N1) U201.D11(P0_D1/TX_D0_P)
TX_D1_N_A: P401.H17(N17) TX_D1_N_A.1(N1) U101.E11(P0_D2/TX_D1_N)
TX_D1_N_B: P402.H17(N17) TX_D1_N_B.1(N1) U201.E11(P0_D2/TX_D1_N)
TX_D1_P_A: P401.H16(N16) TX_D1_P_A.1(N1) U101.D10(P0_D3/TX_D1_P)
TX_D1_P_B: P402.H16(N16) TX_D1_P_B.1(N1) U201.D10(P0_D3/TX_D1_P)
TX_D2_N_A: P401.G16(N16) TX_D2_N_A.1(N1) U101.E10(P0_D4/TX_D2_N)
TX_D2_N_B: P402.G16(N16) TX_D2_N_B.1(N1) U201.E10(P0_D4/TX_D2_N)
TX_D2_P_A: P401.G15(N15) TX_D2_P_A.1(N1) U101.D9(P0_D5/TX_D2_P)
TX_D2_P_B: P402.G15(N15) TX_D2_P_B.1(N1) U201.D9(P0_D5/TX_D2_P)
TX_D3_N_A: P401.D18(N18) TX_D3_N_A.1(N1) U101.E9(P0_D6/TX_D3_N)
TX_D3_N_B: P402.D18(N18) TX_D3_N_B.1(N1) U201.E9(P0_D6/TX_D3_N)
TX_D3_P_A: P401.D17(N17) TX_D3_P_A.1(N1) U101.D8(P0_D7/TX_D3_P)
TX_D3_P_B: P402.D17(N17) TX_D3_P_B.1(N1) U201.D8(P0_D7/TX_D3_P)
TX_D4_N_A: P401.C19(N19) TX_D4_N_A.1(N1) U101.E8(P0_D8/TX_D4_N)
TX_D4_N_B: P402.C19(N19) TX_D4_N_B.1(N1) U201.E8(P0_D8/TX_D4_N)
TX_D4_P_A: P401.C18(N18) TX_D4_P_A.1(N1) U101.D7(P0_D9/TX_D4_P)
TX_D4_P_B: P402.C18(N18) TX_D4_P_B.1(N1) U201.D7(P0_D9/TX_D4_P)
TX_D5_N_A: P401.H20(N20) TX_D5_N_A.1(N1) U101.F8(P0_D10/TX_D5_N)
TX_D5_N_B: P402.H20(N20) TX_D5_N_B.1(N1) U201.F8(P0_D10/TX_D5_N)
TX_D5_P_A: P401.H19(N19) TX_D5_P_A.1(N1) U101.E7(P0_D11/TX_D5_P)
TX_D5_P_B: P402.H19(N19) TX_D5_P_B.1(N1) U201.E7(P0_D11/TX_D5_P)
TX_EXT_LO_A: C337.2(N2) U101.A12(TX_EXT_LO_IN)
TX_EXT_LO_B: C339.2(N2) U201.A12(TX_EXT_LO_IN)
TX_FRAME_N_A: P401.D15(N15) TX_FRAME_N_A.1(N1) U101.H9(TX_FRAME_N)
TX_FRAME_N_B: P402.D15(N15) TX_FRAME_N_B.1(N1) U201.H9(TX_FRAME_N)
TX_FRAME_P_A: P401.D14(N14) TX_FRAME_P_A.1(N1) U101.G9(TX_FRAME_P)
TX_FRAME_P_B: P402.D14(N14) TX_FRAME_P_B.1(N1) U201.G9(TX_FRAME_P)
TX_MON1_A: C101.2(N2) U101.M5(TX_MON1)
TX_MON1_B: C201.2(N2) U201.M5(TX_MON1)
TX_MON2_A: C102.2(N2) U101.A5(TX_MON2)
TX_MON2_B: C202.2(N2) U201.A5(TX_MON2)
TX_VCO_1P1V_SUPPLY_A: C104.2(N2) R123.1(N1) U101.A11(VDDA1P1_TX_VCO) U101.B11(TX_VCO_LDO_OUT)
TX_VCO_1P1V_SUPPLY_B: C204.2(N2) R223.1(N1) U201.A11(VDDA1P1_TX_VCO) U201.B11(TX_VCO_LDO_OUT)
TXNRX_A: P101.2(N2) P401.G19(N19) U101.H4(TXNRX)
TXNRX_B: P201.2(N2) P402.G19(N19) U201.H4(TXNRX)
UNNAMED_2_AD9361_I22_RBIAS: R125.1(N1) U101.L4(RBIAS)
UNNAMED_2_AD9361_I22_RXVCOLDOOU: C116.1(N1) R124.1(N1) U101.G2(RX_VCO_LDO_OUT) U101.G3(VDDA1P1_RX_VCO)
UNNAMED_2_AD9361_I22_XTALN: C165.2(N2) C166.2(N2) U101.M12(XTALN)
UNNAMED_2_ADL5320_I366_RFIN: C156.2(N2) FL102.2(OUT) U104.1(RFIN)
UNNAMED_2_ADL5320_I366_RFOUT: C139.2(N2) C155.2(N2) L110.1(N1) U104.3(RFOUT)
UNNAMED_2_ADL5320_I367_RFIN: C114.2(N2) FL103.2(OUT) U105.1(RFIN)
UNNAMED_2_ADL5320_I367_RFOUT: C115.2(N2) C162.2(N2) L111.1(N1) U105.3(RFOUT)
UNNAMED_2_ADL5521PRELIM_I290__1: FL100.4(IN) U102.7(RFOUT)
UNNAMED_2_ADL5521PRELIM_I290_RF: L106.2(N2) U102.2(RFIN)
UNNAMED_2_ADL5521PRELIM_I290_VB: R108.1(N1) U102.1(VBIAS)
UNNAMED_2_ADL5521PRELIM_I290_VP: C147.2(N2) R108.2(N2) R109.1(N1) U102.8(VPOS)
UNNAMED_2_ADL5521PRELIM_I304__1: FL101.4(IN) U103.7(RFOUT)
UNNAMED_2_ADL5521PRELIM_I304_RF: L108.2(N2) U103.2(RFIN)
UNNAMED_2_ADL5521PRELIM_I304_VB: R110.1(N1) U103.1(VBIAS)
UNNAMED_2_ADL5521PRELIM_I304_VP: C149.2(N2) R110.2(N2) R112.1(N1) U103.8(VPOS)
UNNAMED_2_CAP_I19_N1: C117.1(N1) R124.2(N2)
UNNAMED_2_CAP_I51_N1: C105.1(N1) R123.2(N2)
UNNAMED_2_CAP_I135_N1: C106.1(N1) T106.6(SEC_DOT)
UNNAMED_2_CAP_I136_N1: C107.1(N1) T106.4(SEC)
UNNAMED_2_CAP_I137_N1: C108.1(N1) T105.6(SEC_DOT)
UNNAMED_2_CAP_I138_N1: C109.1(N1) T105.4(SEC)
UNNAMED_2_CAP_I199_N1: C102.1(N1) R122.2(N2)
UNNAMED_2_CAP_I200_N1: C101.1(N1) R121.2(N2)
UNNAMED_2_CAP_I209_N2: C122.2(N2) T107.6(SEC_DOT)
UNNAMED_2_CAP_I210_N2: C123.2(N2) T107.4(SEC)
UNNAMED_2_CAP_I220_N2: C124.2(N2) T108.6(SEC_DOT)
UNNAMED_2_CAP_I221_N2: C125.2(N2) T108.4(SEC)
UNNAMED_2_CAP_I230_N1: C128.1(N1) T101.3(BAL_OUT1)
UNNAMED_2_CAP_I231_N1: C129.1(N1) T101.4(BAL_OUT2)
UNNAMED_2_CAP_I232_N1: C130.1(N1) T102.3(BAL_OUT1)
UNNAMED_2_CAP_I233_N1: C131.1(N1) T102.4(BAL_OUT2)
UNNAMED_2_CAP_I260_N1: C126.1(N1) T103.4(SEC)
UNNAMED_2_CAP_I261_N1: C127.1(N1) T103.6(SEC_DOT)
UNNAMED_2_CAP_I271_N1: C110.1(N1) C140.1(N1) T108.3(PRI_DOT)
UNNAMED_2_CAP_I271_N2: C110.2(N2) C111.1(N1)
UNNAMED_2_CAP_I273_N1: C136.1(N1) C138.1(N1) T107.3(PRI_DOT)
UNNAMED_2_CAP_I273_N2: C136.2(N2) C137.1(N1)
UNNAMED_2_CAP_I281_N2: C142.2(N2) P101.16(N16)
UNNAMED_2_CAP_I341_N2: C132.2(N2) T104.6(SEC_DOT)
UNNAMED_2_CAP_I342_N2: C133.2(N2) T104.4(SEC)
UNNAMED_2_CAP_I345_N2: C138.2(N2) FL102.4(IN)
UNNAMED_2_CAP_I348_N2: C140.2(N2) FL103.4(IN)
UNNAMED_2_CNBNC5P_I182_CNTR: J101.1(CNTR) R101.2(N2) R121.1(N1)
UNNAMED_2_CNBNC5P_I183_CNTR: J102.1(CNTR) R102.2(N2) R122.1(N1)
UNNAMED_2_FLTRBP4PV2_I360_OUT: FL100.2(OUT) T101.1(UNBAL_IN)
UNNAMED_2_FLTRBP4PV2_I361_OUT: FL101.2(OUT) T102.1(UNBAL_IN)
UNNAMED_3_CN160PCDGH_I39_N30: P401.D30(N30) P401.D31(N31)
UNNAMED_3_CN160PCDGH_I54_N35: P401.H35(N35) R404.1(N1)
UNNAMED_3_CN160PCDGH_I216_N30: P402.D30(N30) P402.D31(N31)
UNNAMED_4_ADM7150_I1046_BYP: C538.2(N2) U502.3(BYP)
UNNAMED_4_ADM7150_I1046_REF: C539.2(N2) U502.5(REF_SENSE) U502.6(REF)
UNNAMED_4_ADM7150_I1046_VIN: C534.2(N2) C535.2(N2) C536.2(N2) C644.2(N2) C645.2(N2) C646.2(N2) L502.2(N2) R502.2(N2) U502.7(EN) U502.8(VIN) U508.7(EN) U508.8(VIN)
UNNAMED_4_ADM7150_I1046_VREG: C537.1(N1) U502.1(VREG)
UNNAMED_4_ADM7150_I1142_BYP: C643.2(N2) U508.3(BYP)
UNNAMED_4_ADM7150_I1142_REF: C647.2(N2) U508.5(REF_SENSE) U508.6(REF)
UNNAMED_4_ADM7150_I1142_VREG: C642.1(N1) U508.1(VREG)
UNNAMED_4_ADP237X_I1045_FB: R501.2(N2) R502.1(N1) U501.5(FB)
UNNAMED_4_ADP237X_I1045_SW: L502.1(N1) U501.7(SW)
UNNAMED_4_ADP1755_I730_ADJ: R508.1(N1) R509.2(N2) U504.9(ADJ)
UNNAMED_4_ADP1755_I730_SS: C561.1(N1) U504.7(SS)
UNNAMED_4_ADP1755_I730_VOUT1: C562.1(N1) C563.1(N1) C564.1(N1) C565.1(N1) C566.1(N1) C567.1(N1) R508.2(N2) R510.1(N1) U504.10(VOUT1) U504.11(VOUT2) U504.12(VOUT3) U504.13(VOUT4) U504.14(VOUT5)
UNNAMED_4_ADP1755_I776_ADJ: R512.1(N1) R513.2(N2) U505.9(ADJ)
UNNAMED_4_ADP1755_I776_SS: C577.1(N1) U505.7(SS)
UNNAMED_4_ADP1755_I776_VOUT1: C578.1(N1) C579.1(N1) C580.1(N1) C581.1(N1) C582.1(N1) C583.1(N1) R512.2(N2) R514.1(N1) U505.10(VOUT1) U505.11(VOUT2) U505.12(VOUT3) U505.13(VOUT4) U505.14(VOUT5)
UNNAMED_4_ADP1755_I987_ADJ: R516.1(N1) R517.2(N2) U506.9(ADJ)
UNNAMED_4_ADP1755_I987_SS: C595.1(N1) U506.7(SS)
UNNAMED_4_ADP1755_I987_VOUT1: C514.1(N1) C596.1(N1) C597.1(N1) C598.1(N1) C599.1(N1) C650.1(N1) R516.2(N2) R518.1(N1) U506.10(VOUT1) U506.11(VOUT2) U506.12(VOUT3) U506.13(VOUT4) U506.14(VOUT5)
UNNAMED_4_ADP1755_I997_ADJ: R520.1(N1) R521.1(N1) U507.9(ADJ)
UNNAMED_4_ADP1755_I997_SS: C621.1(N1) U507.7(SS)
UNNAMED_4_ADP1755_I997_VOUT1: C622.1(N1) C623.1(N1) C624.1(N1) C625.1(N1) C626.1(N1) C627.1(N1) R520.2(N2) R522.2(N2) U507.10(VOUT1) U507.11(VOUT2) U507.12(VOUT3) U507.13(VOUT4) U507.14(VOUT5)
UNNAMED_4_ADP2164_I831_FB: R505.2(N2) R506.1(N1) U503.4(FB)
UNNAMED_4_ADP2164_I831_PVIN1: C503.1(N1) C504.1(N1) C505.1(N1) E501.1(N1) E503.1(N1) E504.2(N2) L501.2(N2) R504.2(N2) R523.2(N2) U503.12(PVIN_1) U503.13(PVIN_2)
UNNAMED_4_ADP2164_I831_SW1: L503.1(N1) U503.9(SW_1) U503.10(SW_2) U503.11(SW_3)
UNNAMED_4_ADP2164_I831_SYNC: C549.1(N1) R523.1(N1) U503.1(SYNC) U503.3(TRK) U503.14(VIN)
UNNAMED_4_CAP_I833_N2: C550.2(N2) C551.1(N1) C552.1(N1) E510.1(N1) L503.2(N2)
UNNAMED_4_FERRITE_I816_N2: E1.1(N1) E512.1(N1) E513.2(N2) E514.1(N1) E515.2(N2)
UNNAMED_5_AD7291_I69_DCAP: C313.1(N1) U304.8(DCAP)
UNNAMED_5_AD7291_I69_VIN0: R305.2(N2) R308.2(N2) U304.18(VIN0)
UNNAMED_5_AD7291_I69_VIN1: R304.2(N2) R307.2(N2) U304.19(VIN1)
UNNAMED_5_AD7291_I69_VIN2: R303.2(N2) R306.2(N2) U304.20(VIN2)
UNNAMED_5_AD7291_I69_VIN3: R309.2(N2) R312.2(N2) U304.1(VIN3)
UNNAMED_5_AD7291_I69_VIN4: R310.2(N2) R313.2(N2) U304.2(VIN4)
UNNAMED_5_AD7291_I69_VIN5: R314.2(N2) R327.2(N2) U304.3(VIN5)
UNNAMED_5_AD7291_I69_VIN6: R326.2(N2) R328.2(N2) U304.4(VIN6)
UNNAMED_5_AD7291_I69_VIN7: R325.2(N2) R329.2(N2) U304.5(VIN7)
UNNAMED_5_AD7291_I69_VREF: C314.1(N1) U304.7(VREF)
UNNAMED_5_ADCLK846_I21_CLK: C301.2(N2) C348.2(N2) R360.1(N1) U301.3(CLK)
UNNAMED_5_ADCLK846_I21_CLKN: C302.1(N1) U301.2(CLK_N)
UNNAMED_5_ADCLK846_I21_OUT2: C318.1(N1) U301.18(OUT2)
UNNAMED_5_ADCLK846_I21_OUT2N: C319.1(N1) U301.17(OUT2_N)
UNNAMED_5_ADF5355_I6_CPOUT: C328.2(N2) C329.2(N2) R316.2(N2) U302.7(CPOUT)
UNNAMED_5_ADF5355_I6_CREG1: C327.2(N2) U302.25(CREG1)
UNNAMED_5_ADF5355_I6_CREG2: C326.2(N2) U302.32(CREG2)
UNNAMED_5_ADF5355_I6_RFOUTB: C353.2(N2) R335.2(N2) U302.14(RFOUTB)
UNNAMED_5_ADF5355_I6_RSET: R323.2(N2) U302.22(RSET)
UNNAMED_5_ADF5355_I6_VBIAS: C322.2(N2) C325.2(N2) U302.24(VBIAS)
UNNAMED_5_ADF5355_I6_VREF: C321.2(N2) C324.2(N2) U302.23(VREF)
UNNAMED_5_ADF5355_I6_VTUNE: C330.2(N2) R316.1(N1) U302.20(VTUNE)
UNNAMED_5_ADG91X_I150_RF1: C351.1(N1) U306.8(RF1)
UNNAMED_5_ADG91X_I150_RF2: C352.1(N1) U306.5(RF2)
UNNAMED_5_ADG91X_I150_RFC: U305.4(RFC) U306.4(RFC)
UNNAMED_5_ADG91X_I151_RF1: C349.2(N2) U305.8(RF1)
UNNAMED_5_ADG91X_I151_RF2: C350.2(N2) U305.5(RF2)
UNNAMED_5_CAP_I5_N1: C301.1(N1) J301.1(CNTR) R301.2(N2)
UNNAMED_5_CAP_I98_N1: C329.1(N1) R315.2(N2)
UNNAMED_5_CAP_I121_N1: C336.1(N1) U307.2(DOUT1P)
UNNAMED_5_CAP_I122_N1: C337.1(N1) U307.3(DOUT1N)
UNNAMED_5_CAP_I123_N1: C338.1(N1) U307.11(DOUT2P)
UNNAMED_5_CAP_I124_N1: C339.1(N1) U307.10(DOUT2N)
UNNAMED_5_CAP_I187_N2: C353.1(N1) C390.2(N2) J302.1(CNTR)
UNNAMED_5_DIOLED_I51_P: DS301.A(P) R302.1(N1)
UNNAMED_5_RES_I192_N2: R360.2(N2) Y301.3(OUT)
UNNAMED_9_AD9361_I119_RBIAS: R225.1(N1) U201.L4(RBIAS)
UNNAMED_9_AD9361_I119_RXVCOLDOO: C216.1(N1) R224.1(N1) U201.G2(RX_VCO_LDO_OUT) U201.G3(VDDA1P1_RX_VCO)
UNNAMED_9_AD9361_I119_XTALN: C265.2(N2) C266.2(N2) U201.M12(XTALN)
UNNAMED_9_ADL5320_I225_RFIN: C256.2(N2) FL202.2(OUT) U204.1(RFIN)
UNNAMED_9_ADL5320_I225_RFOUT: C239.2(N2) C255.2(N2) L210.1(N1) U204.3(RFOUT)
UNNAMED_9_ADL5320_I226_RFIN: C214.2(N2) FL203.2(OUT) U205.1(RFIN)
UNNAMED_9_ADL5320_I226_RFOUT: C215.2(N2) C262.2(N2) L211.1(N1) U205.3(RFOUT)
UNNAMED_9_ADL5521PRELIM_I151__1: FL201.4(IN) U203.7(RFOUT)
UNNAMED_9_ADL5521PRELIM_I151_RF: L208.2(N2) U203.2(RFIN)
UNNAMED_9_ADL5521PRELIM_I151_VB: R210.1(N1) U203.1(VBIAS)
UNNAMED_9_ADL5521PRELIM_I151_VP: C249.2(N2) R210.2(N2) R212.1(N1) U203.8(VPOS)
UNNAMED_9_ADL5521PRELIM_I159__1: FL200.4(IN) U202.7(RFOUT)
UNNAMED_9_ADL5521PRELIM_I159_RF: L206.2(N2) U202.2(RFIN)
UNNAMED_9_ADL5521PRELIM_I159_VB: R208.1(N1) U202.1(VBIAS)
UNNAMED_9_ADL5521PRELIM_I159_VP: C247.2(N2) R208.2(N2) R209.1(N1) U202.8(VPOS)
UNNAMED_9_CAP_I23_N2: C225.2(N2) T208.4(SEC)
UNNAMED_9_CAP_I24_N2: C224.2(N2) T208.6(SEC_DOT)
UNNAMED_9_CAP_I30_N2: C222.2(N2) T207.6(SEC_DOT)
UNNAMED_9_CAP_I31_N2: C223.2(N2) T207.4(SEC)
UNNAMED_9_CAP_I50_N2: C233.2(N2) T204.4(SEC)
UNNAMED_9_CAP_I51_N2: C232.2(N2) T204.6(SEC_DOT)
UNNAMED_9_CAP_I55_N1: C227.1(N1) T203.6(SEC_DOT)
UNNAMED_9_CAP_I56_N1: C226.1(N1) T203.4(SEC)
UNNAMED_9_CAP_I69_N1: C207.1(N1) T206.4(SEC)
UNNAMED_9_CAP_I70_N1: C206.1(N1) T206.6(SEC_DOT)
UNNAMED_9_CAP_I71_N1: C209.1(N1) T205.4(SEC)
UNNAMED_9_CAP_I72_N1: C208.1(N1) T205.6(SEC_DOT)
UNNAMED_9_CAP_I92_N1: C202.1(N1) R222.2(N2)
UNNAMED_9_CAP_I96_N1: C201.1(N1) R221.2(N2)
UNNAMED_9_CAP_I101_N1: C205.1(N1) R223.2(N2)
UNNAMED_9_CAP_I111_N1: C217.1(N1) R224.2(N2)
UNNAMED_9_CAP_I126_N2: C242.2(N2) P201.16(N16)
UNNAMED_9_CAP_I165_N1: C231.1(N1) T202.4(BAL_OUT2)
UNNAMED_9_CAP_I167_N1: C230.1(N1) T202.3(BAL_OUT1)
UNNAMED_9_CAP_I168_N1: C229.1(N1) T201.4(BAL_OUT2)
UNNAMED_9_CAP_I170_N1: C228.1(N1) T201.3(BAL_OUT1)
UNNAMED_9_CAP_I178_N1: C210.1(N1) C240.1(N1) T208.3(PRI_DOT)
UNNAMED_9_CAP_I178_N2: C210.2(N2) C211.1(N1)
UNNAMED_9_CAP_I187_N1: C236.1(N1) C238.1(N1) T207.3(PRI_DOT)
UNNAMED_9_CAP_I187_N2: C236.2(N2) C237.1(N1)
UNNAMED_9_CAP_I208_N2: C238.2(N2) FL202.4(IN)
UNNAMED_9_CAP_I210_N2: C240.2(N2) FL203.4(IN)
UNNAMED_9_CNBNC5P_I87_CNTR: J202.1(CNTR) R202.2(N2) R222.1(N1)
UNNAMED_9_CNBNC5P_I93_CNTR: J201.1(CNTR) R201.2(N2) R221.1(N1)
UNNAMED_9_FLTRBP4PV2_I215_OUT: FL200.2(OUT) T201.1(UNBAL_IN)
UNNAMED_9_FLTRBP4PV2_I217_OUT: FL201.2(OUT) T202.1(UNBAL_IN)
VADJ: C618.1(N1) C619.1(N1) E515.1(N1) P401.G39(N39) P401.H40(N40) P402.G39(N39) P402.H40(N40)
XTALN_A: C165.1(N1) U301.24(OUT0)
XTALN_B: C265.1(N1) U301.21(OUT1)
XTALP_A: U101.M11(XTALP)
XTALP_B: U201.M11(XTALP)

Pads without a net: NOREF#14 1; NOREF#16 1; NOREF#17 1; NOREF#18 1; NOREF#19 1; P401 C2 C3 C6 C7 D4 D5 D29 D33 D34 G2 G3 G28 G36 G37 H1 H4 H5 H32 H38; P402 C2 C3 C6 C7 C22 C23 C30 C31 C34 D1 D4 D5 D20 D21 D29 D33 D34 D35 G2 G3 G28 G31 G33 G34 G36 G37 H1 H4 H5 H31 H32 H34 H35 H37 H38; T101 6; T102 6; T201 6; T202 6; U101 A3 M3; U102 3 4 5 6; U103 3 4 5 6; U201 A3 M3; U202 3 4 5 6; U203 3 4 5 6; U301 1 8 9 11 12 20 23; U302 5; U304 12; U504 8; U505 8; U506 8; U507 8

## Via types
v1: diameter 0.508, hole 0.254, TOP to BOTTOM, 1108 vias
v2: diameter 0.305, hole 0.152, TOP to BOTTOM, 254 vias
v3: diameter 0.406, hole 0.203, TOP to BOTTOM, 323 vias

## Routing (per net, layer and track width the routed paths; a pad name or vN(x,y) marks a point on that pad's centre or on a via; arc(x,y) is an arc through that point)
3.3VAUX: length 11.4
  TOP w0.254: U304.10 38.96,49.09 v3(38.87,49.19)
  TOP w0.305: 34.04,48.51 v3(33.97,48.58) ; 34.04,48.51 U304.16 ; 34.04,48.51 34.54,48.01 U304.17
  TOP w0.394: C312.1 C311.2 33.61,48.5 33.69,48.58 v3(33.97,48.58)
  TOP w0.508: 84.44,49.16 v1(85.08,48.52) ; 84.44,119.11 v1(85.08,118.48)
  BOTTOM w0.305: v1(85.08,118.48) 85.26,118.3 R401.2 R402.2 ; U303.8 88.33,73.65 88.34,73.66 88.2,73.8 C310.1 88.2,74.84 v3(88.4,75.04)
5V: length 18.6
  TOP w0.394: E509.1 E507.1 ; v1(53.63,55.77) 54.5,55.77 56.1,57.37 U502.2
  BOTTOM w0.394: 28.72,44.28 21.84,51.17 TP306.1 ; R309.1 31.87,43.3
  vias: v1(52.1,55.77) v1(52.84,55.77)
12V: length 25.9
  TOP w0.305: U501.4 67.69,67.36 v3(67.47,67.58) ; U501.1 70.41,66.59
  TOP w0.394: 75.76,65.27 P501.3 ; P501.3 76.84,66.35 ; P501.3 77.92,65.27 ; P501.3 76.84,64.19
  TOP w0.508: v3(85.12,56.12) 85.71,55.53 P402.C37 ; P402.C37 85.69,55.51 v3(85.1,54.92) ; P402.C37 v1(86.88,55.51) ; 85.69,52.97 85.69,52.99 85.1,53.58 v3(85.1,53.58) ; 85.69,52.97 85.1,52.38 v3(85.1,52.38) ; 85.69,52.97 P402.C35 v1(86.88,52.97) ; P401.C37 v1(86.88,125.46) ; P401.C37 85.69,125.46 v3(85.1,124.87) ; P401.C37 85.71,125.49 v3(85.12,126.08) ; v1(86.88,122.92) P401.C35 85.69,122.92 85.69,122.94 85.1,123.53 v3(85.1,123.54)
  L3_PWR w0.508: 75.76,65.27 P501.3 ; P501.3 76.84,66.35 ; P501.3 77.92,65.27 ; P501.3 76.84,64.19
  L8_PWR w0.508: 75.76,65.27 P501.3 ; P501.3 76.84,64.19 ; P501.3 76.84,66.35 ; P501.3 77.92,65.27
  vias: v1(74.81,64.12) v1(74.84,63.28) v1(75.85,64.07) v1(75.83,63.28) v3(85.1,122.33)
GND_POWER: length 984.3
  TOP w0.203: v2(20.41,111.4) 21.78,111.4 v2(21.94,111.23) U101.A6 v2(21.54,110.26) ; v2(28.56,117.29) 29.17,116.69 v2(29.17,115.2) v2(29.73,114.63) v2(30.3,114.06) 30.42,114.06 v2(30.99,113.49) v2(31.56,112.93)
  TOP w0.254: v2(29.46,26.15) 29.93,26.15 30.44,25.63 30.44,25.36 C545.2 ; U304.9 39.75,48.01 v3(39.91,48.17) ; v2(25.34,108.97) 25.34,108.5 24.82,107.99 24.54,107.99 C569.2
  TOP w0.305: v3(33.82,72.53) 34.13,72.22 U307.4 ; U506.6 v3(52.37,63.2) ; C313.2 40.16,48.83 39.91,48.58 v3(39.91,48.17) ; C325.1 21.45,76.42 v1(21.7,76.67) ; U507.6 52.39,67.54 v1(52.06,67.22) ; U302.8 26.95,67.74 v3(27.26,67.42) ; v2(27.55,118.26) 27.26,117.97 26.88,117.97 C585.2 ; U302.31 21.98,69.4 21.22,68.64 21.12,68.64 20.69,68.21 v3(20.69,68.18) ; v1(29.78,68.31) 29.5,68.59 C308.2 ; v3(37.32,69.88) U307.14 ; U307.9 34.13,67.89 v3(33.89,67.65) ; v1(69.43,62.5) 69.43,62.7 69.19,62.94 U501.8 ; v3(36,72.56) 35.63,72.18 U307.1 ; U302.13 28.69,70.9 v3(28.74,70.85) ; U301.6 v1(12.31,68.24) ; U304.6 39.62,46.51 v3(39.83,46.29) 39.83,45.43 40.35,44.91 C314.2 ; v1(63.51,85.89) 63.51,84.82 63.83,84.5 U503.5 ; C324.1 23.55,76.57 v1(23.4,76.72) ; U302.9 28.1,68.9 v3(28.38,68.62) ; U503.6 63.32,83.85 v1(62.92,83.45) ; C589.2 27.83,108.4 v2(27.03,108.4) ; U501.2 68.69,67.38 v3(68.88,67.58) ; U307.8 32.95,69.38 v3(32.49,68.92) 32.34,69.08 R350.1 ; U301.7 v1(14.01,66.61) ; U302.21 24.95,70.9 v1(25.2,70.65) 26.45,71.9 U302.18 ; U503.8 64.02,82.55 v1(63.71,82.86) 64.05,83.2 U503.7 ; U307.5 32.78,70.88 v3(32.49,71.16) ; v3(35.95,67.78) 35.63,68.1 U307.12 ; C323.1 v1(28.1,76.77) ; U503.2 66.91,86.17 v3(67.11,86.37) ; U504.6 v3(52.36,83.57) ; U302.15 v3(28.74,71.9) ; U505.6 v3(52.35,76.79)
  TOP w0.356: C104.1 v1(24.62,105.3)
  TOP w0.394: C217.2 19.31,20.39 v1(19.31,18.49) ; C623.2 v1(46.39,67.86) ; C335.2 v1(39.2,69.15) ; v1(17.05,74.1) 16.64,73.69 C303.2 ; C514.2 C650.2 45.87,55.76 ; C514.2 v1(46.78,55.76) ; C514.2 C599.2 47.7,55.76 ; C595.2 v1(50.53,63.82) ; R335.1 30.65,72.93 v1(30.9,73.19) 30.76,73.33 C306.2 ; v1(61.65,85.94) 61.27,85.56 C554.1 ; C501.2 74.15,78.98 v1(73.92,79.21) 73.45,78.73 C502.2 ; 74.84,66.05 74.89,66.05 76.64,67.81 ; 74.84,66.05 75.79,67.01 76.59,67.81 76.64,67.81 ; 74.84,66.05 C530.1 74.33,66.05 ; C626.2 C627.2 45.89,62.56 ; C626.2 v1(46.8,62.56) ; C626.2 C624.2 47.71,62.56 ; T204.1 14.24,39.02 12.83,39.02 ; C607.2 20.86,25.02 v2(21.54,25.02) ; 33.05,28.74 33.33,29.02 v3(33.33,29.73) 32.55,30.52 31.57,30.52 C632.2 31.15,30.1 31.15,29.69 C635.2 ; R207.2 v3(65.82,52.68) 66.23,53.1 C539.1 ; C609.2 31.43,24.74 v3(31.92,24.26) ; v2(28.17,22.35) 28.91,22.35 C525.2 ; C593.2 19.44,114.23 19.44,113.73 v2(19.68,113.49) ; C581.2 48.92,69.93 49.31,69.53 v1(49.51,69.53) ; C505.2 72.52,83.55 v1(72.65,83.43) ; v1(72.96,62.12) 73.26,62.42 C533.1 ; v1(36.38,112.86) 36.86,112.86 37.13,113.13 ; v1(16.21,116.57) 16.68,117.04 C120.1 ; C117.2 20.58,118.12 19.59,119.12 v1(17.68,119.12) ; v1(45.59,69.32) 45.84,69.57 C583.2 ; C551.2 63.43,82.58 v1(63.71,82.86) ; C521.2 21.54,109.52 v2(21.54,110.26) 22.29,110.26 C520.2 ; C244.2 v3(68.36,52.68) ; R211.1 23.24,24.07 v2(23.24,23.32) ; C555.2 61.27,87.36 v1(61.76,87.85) ; C647.1 61.88,74.87 v1(61.27,75.48) ; C542.1 C541.1 49.84,52.29 49.46,51.9 ; J302.2 39.34,84.54 ; J302.2 39.34,82 ; J302.2 40.61,83.27 ; J302.2 38.07,83.27 ; R509.1 v1(46.08,82.08) ; C562.2 v1(47.61,81.19) ; v3(16.21,24.4) 16.21,24.42 16.45,24.66 16.46,24.66 16.8,25 C517.2 17.49,25.69 C546.2 ; v2(19.79,115.61) 19.79,115.96 C571.2 ; C566.2 v1(47.68,76.16) ; T204.5 v3(17.01,38.04) 15.66,39.39 ; 72.35,49.27 P201.26 ; P201.26 73.43,48.19 ; P201.26 73.43,50.35 ; P201.26 74.51,49.27 ; v1(7.81,68.08) 7.91,68.19 R301.1 ; v1(20.25,75.6) 20.88,74.97 C322.1 ; v1(64.83,64.48) 64.3,65.01 C534.1 ; C628.2 23.31,20.59 22.49,20.59 22.21,20.86 22.68,21.32 v2(22.94,21.32) 22.94,21.63 C515.2 ; R205.2 v3(63.28,52.68) ; v1(71.2,113.37) 70.75,113.37 70.62,113.5 C145.2 ; C121.2 16.83,115.44 16.24,114.85 v1(16.24,114.59) ; v1(58.13,69.91) 58.38,69.65 C644.1 ; C524.2 27.81,22.75 v2(27.2,22.75) ; J302.4 33.43,83.27 ; J302.4 32.16,82 ; J302.4 32.16,84.54 ; J302.4 30.89,83.27 ; v1(23.38,106.44) 23.93,107 C568.2 ; C243.2 v3(68.33,43.35) ; v1(9.56,12.18) 9.53,12.15 R201.1 ; R104.2 63.01,113.74 v1(63.41,113.35) ; C245.2 v3(70.91,43.37) ; R202.1 64.6,12.43 v1(64.95,12.08) ; C643.1 v1(69.85,74.72) ; C547.1 49.46,51.9 ; 49.46,51.9 49.99,51.9 v1(50.07,51.83) ; C577.2 v1(50.51,77.41) ; C621.2 51.11,70.28 v1(50.87,70.04) ; C630.2 20.29,26.71 v2(19.85,26.71) ; C646.1 C645.1 64.75,66.78 64.95,66.59 R501.1 v1(66.53,66.59) ; C617.2 26.07,29.72 v2(26.07,29.54) ; C317.1 v3(24.54,65.39) ; R101.1 v1(62.63,130.62) ; v1(16.01,29.4) 16.01,28.98 C235.2 ; C620.2 v1(54.74,77.99) ; C549.2 v1(68.54,87.11) ; v1(63.46,87.8) 64.07,87.19 R505.1 ; C564.2 v1(46.77,76.16) ; C561.2 v1(50.52,84.23) ; v1(59.7,90.06) 59.39,89.75 C560.2 ; R513.1 v1(46.2,75.26) ; v2(20.51,115.49) 20.82,115.49 C570.2 ; v1(23.58,122.24) 23.76,122.24 C573.2 24.35,121.65 C574.2 24.35,120.27 24.57,120.05 C572.2 ; v2(29.13,110.26) 29.28,110.26 30.02,109.53 C613.2 31.1,109.26 31.1,109.03 C612.2 ; C629.2 29.73,32.02 v3(29.73,32.32) ; C608.2 19.85,25.71 v2(19.85,25.58) ; C556.2 59.27,88.56 v1(59.77,89.07) ; v3(13.97,16.25) 13.97,15.2 T203.1 ; v3(13.97,16.25) 13.97,16.99 T203.5 ; v3(13.97,16.25) 13.23,16.25 T203.2 11.41,14.43 ; C579.2 v1(47.6,74.37) ; C119.2 38.46,114.96 v1(38.46,114.67) ; C135.2 28.24,122.49 v1(28.46,122.49) ; C348.1 v1(9.5,68.15) ; v1(44.53,51.7) 44.74,51.9 C548.1 45.65,52.32 45.71,52.39 C544.1 C543.1 ; C305.2 15.6,75.73 v1(15.86,75.98) ; U508.4 67.83,73.27 v1(67.19,72.63) ; v1(13.16,126.53) 14.11,126.53 T103.2 15.98,124.65 ; C328.1 26.63,64.71 25.94,64.02 R315.1 v1(25.94,62.19) ; C688.1 v1(74.58,75.5) ; 75.78,67.35 P501.2 ; P501.2 77.92,67.81 ; P501.2 76.64,67.81 ; C596.2 v1(46.38,60.73) ; C311.1 33.27,49.96 v3(34.96,51.65) ; v1(46.5,69.32) 46.76,69.57 C580.2 ; J302.3 35.75,88.13 ; J302.3 34.48,86.86 ; J302.3 35.75,85.59 ; J302.3 37.02,86.86 ; v1(31.63,103.54) C587.2 31.19,104.98 C586.2 ; C578.2 v1(46.35,74.32) ; C532.1 v1(72.17,62.14) ; v1(7.63,71.2) 8.16,71.73 Y301.2 ; v1(23.4,76.72) 22.99,76.31 C321.1 ; v2(24.2,116.89) 23.88,117.21 23.88,117.49 C575.2 ; C588.2 28.86,107.3 29.27,107.3 C590.2 30.11,106.47 C591.2 30.11,105.04 v1(29.9,104.84) ; C598.2 v1(48.64,55.76) ; 29.74,28.92 30.03,28.64 v2(30.03,27.84) 30.75,27.84 30.78,27.81 ; C625.2 v1(48.65,62.56) ; C567.2 v1(48.62,76.16) ; R111.1 23.26,115.19 v2(22.51,115.19) ; v1(47.25,67.78) 47.25,67.73 47.64,67.34 C622.2 ; R521.2 v1(46.06,68.48) ; C134.1 27.39,120.18 26.78,120.18 C584.2 26.37,119.78 26.37,119.24 v2(26.47,119.15) ; 74.33,66.05 74.35,66.08 C642.2 C648.1 74.35,72.53 74.63,72.81 v1(74.63,73.57) C649.1 ; 74.33,66.05 74.12,66.05 ; C631.2 23.53,18.53 C221.2 24.48,17.58 v3(24.5,17.58) 25.03,17.58 C220.1 ; C346.2 v1(11.29,77) ; P101.26 74.25,119.23 ; P101.26 73.17,118.15 ; P101.26 73.17,120.31 ; P101.26 72.09,119.23 ; v1(28.84,74.99) 28.44,74.99 28.2,74.75 C309.1 ; C144.2 v1(68.09,122.7) ; v1(26.6,104.74) 27.16,105.29 C105.2 ; R206.2 v3(65.82,43.35) ; v1(7.25,125.45) 7.6,125.1 R102.1 ; C504.2 v1(72.63,82.56) ; T104.2 v3(37.23,121.42) T104.5 ; v1(16.57,74.66) 16.57,74.69 16.09,74.21 C304.2 ; 10.45,115.18 10.45,115.43 ; R204.2 v3(63.28,43.35) ; v3(30.61,45.53) 30.9,45.81 C312.2 ; C347.2 v1(10.07,75.81) ; C565.2 v1(45.85,76.16) ; v1(22.36,67.22) 22.59,66.99 R406.2 22.58,66.32 C326.1 ; C302.2 v1(12.61,72.28) ; R107.2 v1(65.54,122.66) ; v3(20.69,68.18) 20.64,68.23 20.36,68.23 20.04,68.55 R351.2 ; C327.1 v3(19.41,73.39) ; J302.5 35.75,80.95 ; J302.5 37.02,79.68 ; J302.5 35.75,78.41 ; J302.5 34.48,79.68 ; v3(16.77,113.93) 17.41,114.57 17.51,114.57 17.99,115.05 ; C637.2 18.06,27.78 C633.2 18.56,27.28 v2(19.28,27.28) ; C234.1 28.87,32.24 28.87,32.88 C636.2 29.15,33.72 v3(29.34,33.72) ; v1(47.42,69.32) 47.67,69.57 C582.2 ; C540.1 55.3,54.69 v1(55.64,55.02) C538.1 57.01,55.02 57.19,54.83 U502.4 ; C651.1 v1(74.58,74.54) ; C219.2 23.01,34.03 23.78,33.26 v1(23.78,33.16) 24.14,33.52 24.21,33.52 C218.1 ; C330.1 v3(31.29,65.96) ; 15.98,124.65 v1(15.98,124.6) 15.9,124.51 14.33,124.51 T103.1 ; 15.98,124.65 T103.5 ; C116.2 23.07,117.1 v2(23.07,116.89) ; v2(21.54,23.88) 21.33,23.88 C216.2 ; C334.2 v1(39.12,70.09) ; C594.2 v1(51.06,57.01) ; R106.2 65.56,113.53 65.68,113.4 v1(66.05,113.4) ; C550.1 60.46,82.02 60.24,82.23 C553.1 v1(61.37,83.17) 62.24,82.31 C552.2 ; C143.2 68.1,113.5 68.23,113.37 v1(68.56,113.37) ; C563.2 v1(46.36,81.14) ; C597.2 v1(47.62,60.78) ; T104.1 38.36,124.34 v1(38.36,125.85) ; C333.2 v1(39.64,72.26) ; C320.1 v1(28.84,75.73) ; R105.2 v1(63.05,122.59) ; C576.2 v1(54.74,76.24) ; R323.1 v1(24.67,76.42) ; C307.2 v3(19.31,72.28) ; C537.2 57.77,64.87 v1(57.02,65.62) 59.12,65.62 59.65,65.09 C536.1 C535.1 ; C531.1 v1(71.05,62.14) ; R517.1 v1(45.47,61.67)
  TOP w0.508: P402.H3 v1(78.2,12.33) ; 79.36,39 v1(78.2,39) ; P402.C33 v1(86.88,50.43) ; 85.71,28.84 v1(86.88,28.84) ; P402.D2 v1(83.28,11.06) ; P402.C25 v1(86.88,40.27) ; P402.G32 v1(81.8,49.16) ; v1(85.07,46.03) 85.71,45.39 P402.C29 v1(86.88,45.35) ; 84.44,114.03 v1(83.28,114.03) 82.01,115.3 P401.G29 ; P402.G23 v1(81.8,37.73) ; 79.36,58.05 v1(78.2,58.05) ; 84.44,106.41 v1(83.28,106.41) ; P401.D19 v1(83.28,102.6) ; 79.36,50.43 v1(78.2,50.43) ; 80.63,79.74 v1(81.8,79.74) ; P401.G26 82.01,111.49 v1(83.28,110.22) 84.44,110.22 ; P401.H2 v1(78.2,81.01) ; P402.H9 v1(78.2,19.95) ; P401.C28 v1(86.88,114.03) ; v1(80.63,60.21) P402.G40 ; P402.G35 v1(81.8,52.97) ; P401.C36 v1(86.88,124.19) ; 85.71,13.6 v1(86.88,13.6) ; P401.C24 v1(86.88,108.95) ; 85.71,84.82 v1(86.88,84.82) ; P401.C20 v1(86.88,103.87) ; P401.H15 v1(78.2,97.52) ; 84.44,55.51 v1(83.28,55.51) ; 79.36,112.76 v1(78.2,112.76) ; 85.71,30.11 v1(86.88,30.11) ; P402.C32 v1(86.88,49.16) ; v1(80.63,130.16) P401.G40 ; C503.2 73.08,81.34 v1(74.07,82.33) ; 85.71,89.9 v1(86.88,89.9) ; P401.C38 v1(86.88,126.73) ; 84.44,128 v1(82.41,128) ; 79.36,46.62 78.22,46.62 v1(78.09,46.74) ; 85.71,25.03 v1(86.88,25.03) ; 84.44,36.46 v1(83.28,36.46) ; P402.C28 v1(86.88,44.08) ; 85.71,83.55 v1(86.88,83.55) ; 79.36,128 v1(78.2,128) ; 80.63,22.49 v1(81.8,22.49) ; 80.63,100.06 v1(81.8,100.06) ; P401.D6 v1(83.28,86.09) ; 84.44,44.08 v1(83.28,44.08) ; P402.D3 v1(83.28,12.33) ; P402.C36 v1(86.88,54.24) ; 79.36,120.38 v1(78.2,120.38) ; 85.71,98.79 v1(86.88,98.79) ; P401.C21 v1(86.88,105.14) ; 85.71,88.63 v1(86.88,88.63) ; 84.44,125.46 v1(83.28,125.46) ; 80.63,83.55 v1(81.8,83.55) ; P402.D16 v1(83.28,28.84) ; 84.44,40.27 v1(83.28,40.27) ; 85.71,14.87 v1(86.88,14.87) ; P401.D16 v1(83.28,98.79) ; 85.71,9.79 v1(86.88,9.79) ; P402.H18 v1(78.2,31.38) ; 85.71,23.76 v1(86.88,23.76) ; P401.H12 v1(78.2,93.71) ; P401.G38 v1(81.8,126.73) ; P401.G35 v1(81.8,122.92) ; P402.C24 v1(86.88,39) ; 79.36,116.57 v1(78.2,116.57) ; 79.36,35.19 v1(78.2,35.19) ; P401.D7 v1(83.28,87.36) ; P402.D10 v1(83.28,21.22) ; P402.D6 v1(83.28,16.14) ; P401.H9 v1(78.2,89.9) ; P402.D13 v1(83.28,25.03) ; P402.C40 v1(86.88,59.32) ; 79.36,124.19 v1(78.2,124.19) ; 80.63,88.63 v1(81.8,88.63) ; v1(85.07,115.99) 85.71,115.35 P401.C29 v1(86.88,115.3) ; P402.G38 v1(81.8,56.78) ; 85.71,94.98 v1(86.88,94.98) ; P402.H12 v1(78.2,23.76) ; 80.63,14.87 v1(81.8,14.87) ; P401.D2 v1(83.28,81.01) ; P401.D10 v1(83.28,91.17) ; 85.71,18.68 v1(86.88,18.68) ; P401.C32 86.34,119.11 v1(86.9,119.67) 86.19,120.38 P401.C33 ; 79.36,54.24 v1(78.2,54.24) ; 85.71,79.74 v1(86.88,79.74) ; P402.C20 v1(86.88,33.92) ; P401.G32 v1(81.8,119.11) ; P402.D19 v1(83.28,32.65) ; P401.C25 v1(86.88,110.22) ; P401.D13 v1(83.28,94.98) ; 79.36,108.95 v1(78.2,108.95) ; 80.63,13.6 v1(81.8,13.6) ; 85.71,100.06 v1(86.88,100.06) ; 85.71,35.19 v1(86.88,35.19) ; P401.G20 v1(81.8,103.87) ; P402.G20 v1(81.8,33.92) ; P402.G29 v1(81.8,45.35) ; P401.C40 v1(86.88,129.27) ; 84.44,17.41 v1(83.28,17.41) ; P402.C38 v1(86.88,56.78) ; 80.63,96.25 v1(81.8,96.25) ; 80.63,18.68 v1(81.8,18.68) ; P401.H21 v1(78.2,105.14) ; 80.63,26.3 v1(81.8,26.3) ; P402.G26 v1(81.8,41.54) ; P401.D3 v1(83.28,82.28) ; 80.63,92.44 v1(81.8,92.44) ; P401.G23 v1(81.8,107.68) ; 80.63,30.11 v1(81.8,30.11) ; 85.71,93.71 v1(86.88,93.71) ; P402.H15 v1(78.2,27.57) ; P402.H6 v1(78.54,16.96) ; 80.63,84.82 v1(81.8,84.82) ; 84.44,58.05 v1(83.28,58.05) ; P402.H2 v1(78.2,11.06) ; P401.H18 v1(78.2,101.33) ; P401.H6 v1(78.54,86.92) ; P401.H3 v1(78.2,82.28) ; 80.63,9.79 v1(81.8,9.79) ; 85.71,19.95 v1(86.88,19.95) ; 79.36,42.81 v1(78.2,42.81)
  L2_GND w0.394: 34.48,79.68 J302.5 ; J302.5 35.75,78.41 ; J302.5 35.75,80.95 ; J302.5 37.02,79.68 ; P201.26 74.51,49.27 ; P201.26 73.43,50.35 ; P201.26 73.43,48.19 ; P201.26 72.35,49.27 ; 35.75,85.59 J302.3 ; J302.3 37.02,86.86 ; J302.3 34.48,86.86 ; J302.3 35.75,88.13 ; P101.26 73.17,120.31 ; P101.26 74.25,119.23 ; P101.26 73.17,118.15 ; P101.26 72.09,119.23 ; 75.76,67.81 P501.2 ; P501.2 76.84,68.89 ; P501.2 76.84,66.73 ; P501.2 77.92,67.81 ; 39.34,82 J302.2 ; J302.2 38.07,83.27 ; J302.2 40.61,83.27 ; J302.2 39.34,84.54 ; 32.16,82 J302.4 ; J302.4 33.43,83.27 ; J302.4 32.16,84.54 ; J302.4 30.89,83.27
  L4_GND w0.394: 72.09,119.23 P101.26 ; P101.26 74.25,119.23 ; P101.26 73.17,120.31 ; P101.26 73.17,118.15 ; J302.3 35.75,88.13 ; J302.3 37.02,86.86 ; J302.3 35.75,85.59 ; J302.3 34.48,86.86 ; J302.4 33.43,83.27 ; J302.4 32.16,82 ; J302.4 30.89,83.27 ; J302.4 32.16,84.54 ; 35.75,78.41 J302.5 ; J302.5 34.48,79.68 ; J302.5 35.75,80.95 ; J302.5 37.02,79.68 ; 39.34,82 J302.2 ; J302.2 38.07,83.27 ; J302.2 39.34,84.54 ; J302.2 40.61,83.27 ; 73.43,48.19 P201.26 ; P201.26 72.35,49.27 ; P201.26 73.43,50.35 ; P201.26 74.51,49.27 ; 75.76,67.81 P501.2 ; P501.2 76.84,66.73 ; P501.2 76.84,68.89 ; P501.2 77.92,67.81
  L5_SIG w0.394: 32.16,82 J302.4 ; J302.4 30.89,83.27 ; J302.4 32.16,84.54 ; J302.4 33.43,83.27 ; 39.34,82 J302.2 38.07,83.27 ; P501.2 76.84,68.89 ; P501.2 77.92,67.81 ; P501.2 75.76,67.81 ; P501.2 76.84,66.73 ; 35.75,85.59 J302.3 34.48,86.86 ; J302.5 37.02,79.68 ; J302.5 34.48,79.68 ; J302.5 35.75,78.41 ; J302.5 35.75,80.95
  L6_SIG w0.394: 32.16,82 J302.4 ; J302.4 30.89,83.27 ; J302.4 32.16,84.54 ; J302.4 33.43,83.27 ; 34.48,86.86 J302.3 ; J302.3 37.02,86.86 ; J302.3 35.75,88.13 ; J302.3 35.75,85.59 ; J302.2 40.61,83.27 ; J302.2 38.07,83.27 ; J302.2 39.34,82 ; J302.2 39.34,84.54 ; J302.5 37.02,79.68 ; J302.5 34.48,79.68 ; J302.5 35.75,78.41 ; J302.5 35.75,80.95 ; P501.2 76.84,68.89 ; P501.2 75.76,67.81 ; P501.2 76.84,66.73 ; P501.2 77.92,67.81
  L7_GND w0.394: 34.48,86.86 J302.3 ; J302.3 35.75,85.59 ; J302.3 37.02,86.86 ; J302.3 35.75,88.13 ; 30.89,83.27 J302.4 ; J302.4 33.43,83.27 ; J302.4 32.16,84.54 ; J302.4 32.16,82 ; 75.76,67.81 P501.2 ; P501.2 77.92,67.81 ; P501.2 76.84,66.73 ; P501.2 76.84,68.89 ; 38.07,83.27 J302.2 ; J302.2 40.61,83.27 ; J302.2 39.34,84.54 ; J302.2 39.34,82 ; J302.5 37.02,79.68 ; J302.5 35.75,78.41 ; J302.5 35.75,80.95 ; J302.5 34.48,79.68 ; P201.26 73.43,50.35 ; P201.26 74.51,49.27 ; P201.26 73.43,48.19 ; P201.26 72.35,49.27 ; 73.17,118.15 P101.26 ; P101.26 73.17,120.31 ; P101.26 72.09,119.23 ; P101.26 74.25,119.23
  L9_GND w0.394: J302.2 40.61,83.27 ; J302.2 39.34,82 ; J302.2 38.07,83.27 ; J302.2 39.34,84.54 ; P501.2 76.84,68.89 ; P501.2 76.84,66.73 ; P501.2 77.92,67.81 ; P501.2 75.76,67.81 ; 73.17,118.15 P101.26 ; P101.26 72.09,119.23 ; P101.26 74.25,119.23 ; P101.26 73.17,120.31 ; 72.35,49.27 P201.26 ; P201.26 73.43,50.35 ; P201.26 74.51,49.27 ; P201.26 73.43,48.19 ; J302.4 32.16,84.54 ; J302.4 32.16,82 ; J302.4 30.89,83.27 ; J302.4 33.43,83.27 ; 35.75,78.41 J302.5 ; J302.5 37.02,79.68 ; J302.5 35.75,80.95 ; J302.5 34.48,79.68 ; 34.48,86.86 J302.3 ; J302.3 37.02,86.86 ; J302.3 35.75,85.59 ; J302.3 35.75,88.13
  L9_GND w0.508: 10.62,71.16 10.62,71.8
  BOTTOM w0.178: v2(25.34,108.97) v2(24.77,109.53) v2(24.2,110.1) v2(23.64,110.66) v2(23.07,111.23) v2(24.77,112.93) 25.73,113.89 25.73,113.9 25.74,113.9 v2(25.9,114.06) 25.9,114.07 26.63,114.8 26.63,114.8 26.86,115.03 26.86,115.03 27.19,115.36 27.2,115.36 27.43,115.59 27.43,115.59 27.76,115.93 27.76,115.93 27.99,116.16 27.99,116.16 28.03,116.2 v2(28.15,116.2) ; v2(29.46,26.15) v2(28.9,25.58) v2(28.33,25.02) v2(27.77,24.45) v2(27.2,23.88) v2(25.5,25.58) 24.54,26.54 24.53,26.54 24.53,26.55 v2(24.37,26.71) 24.36,26.71 23.63,27.44 23.63,27.44 23.4,27.67 23.4,27.67 23.07,28.01 23.07,28.01 22.84,28.24 22.84,28.24 22.5,28.57 22.5,28.57 22.27,28.8 22.27,28.8 22.23,28.84 v2(22.23,28.96) ; v2(27.03,108.4) v2(26.47,107.84) v2(25.9,107.27) ; U201.C11 U201.C12 ; U201.M6 21.57,28.95 22.19,28.95 22.66,29.42 22.68,29.42 v2(23.24,29.98) v2(23.8,30.54) v2(24.37,31.11) 24.37,31.23 v2(24.94,31.8) v2(25.5,32.37) ; v2(29.17,115.2) 28.61,115.75 28.61,115.77 28.14,116.24 28.14,116.86 U101.M6 ; U101.C11 U101.C12 ; v2(31.16,26.71) 30.56,27.31
  BOTTOM w0.203: v2(25.34,108.97) U101.C11 ; v2(24.37,26.71) 24.37,27.28 ; v2(26.47,107.84) 26.47,108.13 U101.C12 ; 30.56,27.31 30.56,27.28 30.3,27.28 U201.C12 ; 24.37,30.67 24.37,30.68 v2(24.37,31.11) ; v2(27.03,108.4) U101.D12 ; v2(24.94,31.8) U201.L11 ; v2(25.9,114.06) U101.H7 ; v2(24.77,112.93) U101.F7 ; v2(25.5,25.58) U201.F7
  BOTTOM w0.254: U201.L12 v2(25.5,32.37) ; v2(20.17,28.36) 20.41,28.12 U201.M4 ; U201.C9 v2(28.33,25.02) ; v2(24.2,116.89) 24.2,116.89 U101.J2 ; v2(22.23,28.96) 22.24,28.98 U201.L7 ; U101.H2 23.07,116.89 v2(23.07,116.89) ; v2(31.16,26.71) 31.16,26.71 U201.B12 ; v2(28.9,25.58) 28.9,25.58 U201.C10 ; v2(19.79,115.61) 19.79,115.07 U101.C1 ; U201.K2 v2(19.85,25.58) 19.85,25.58 U201.L2 ; U101.L2 v2(24.77,118.58) 24.77,118.58 U101.K2 ; U201.C7 v2(27.2,23.88) ; U101.C7 v2(23.07,111.23) ; U201.D12 v2(30.03,27.84) 30.56,27.31 v2(30.56,27.34) ; U201.C1 23.2,21.06 v2(22.94,21.32) 23.08,21.46 U201.D1 ; U101.G12 v2(29.13,110.26) ; v2(19.85,26.71) U201.L3 ; R125.2 27.89,118.7 27.89,118.58 27.57,118.26 v2(27.55,118.26) 27.31,118.02 U101.M4 ; v2(28.33,28.41) U201.F11 ; v2(19.68,113.49) U101.B2 ; U101.L7 28.16,116.19 v2(28.15,116.2) ; v2(27.2,22.75) U201.A6 v2(28.17,22.35) ; U201.L9 23.81,30.54 v2(23.8,30.54) ; v2(28.17,29.94) 27.97,29.74 U201.G12 ; U201.H2 v2(21.54,23.88) ; U201.H10 v2(26.07,29.54) ; v2(25.9,118.58) U101.L3 ; U201.C11 v2(29.46,26.15) ; v2(24.77,109.53) 24.77,109.53 25.34,109.53 ; U101.B1 v2(20.24,114.06) U101.C2 ; U201.F3 v2(23.24,23.32) ; v2(27.2,27.28) U201.F9 ; U101.H3 v2(23.64,116.32) ; v2(25.5,22.19) U201.C4 ; U101.L10 30.29,114.06 v2(30.3,114.06) ; U201.K12 v2(26.07,31.8) ; U101.L11 v2(30.99,113.49) ; U101.L8 29.16,115.19 v2(29.17,115.2) ; v2(21.38,112.93) U101.C4 ; v2(26.47,111.23) U101.F9 ; v2(23.24,29.98) 23.24,29.97 U201.L8 ; U101.F3 v2(22.51,115.19) ; U101.H10 v2(28.73,112.36) ; U201.C8 v2(27.77,24.45) ; v2(20.41,111.4) U101.A4 ; U101.L9 29.73,114.62 v2(29.73,114.63) ; v2(25.34,114.62) U101.H6 ; U101.C8 v2(23.64,110.66) ; v2(27.6,110.1) U101.F11 ; v2(21.54,25.02) U201.J2 ; U101.K12 v2(30.99,112.36) ; v2(23.81,26.15) U201.H6 ; v2(22.11,24.45) U201.H3 ; U101.L12 v2(31.56,112.93) ; v2(20.51,115.49) U101.D1 ; U201.B1 v2(24.94,20.49) U201.B2 ; v2(21.94,111.23) U101.A6 v2(21.54,110.26) ; U101.B12 v2(25.9,107.27) ; v2(27.03,21.22) U201.A4 ; U101.C9 v2(24.2,110.1) ; v2(24.37,21.06) 24.37,21.62
  BOTTOM w0.305: v1(20.43,63.06) 20.29,63.2 U306.7 ; v3(19.11,83.6) R319.2 ; C345.2 24.36,62.4 24.38,62.42 C344.2 24.38,63.45 v3(24.52,63.59) ; U303.3 87.03,65.24 v1(86.67,64.88) 86.38,65.18 U303.4 ; C310.2 87.59,74.81 v3(87.43,74.97) ; U306.3 19.64,60.71 v1(19.85,60.92) ; U305.3 v1(20.36,79.99) ; U303.7 v3(87.68,73.39) ; v1(15.73,77.84) 16.01,78.12 C342.2 16.01,79.15 C341.2 ; v1(19.49,77.99) 19.71,77.77 U305.7 ; v1(19.44,63.06) 19.64,63.25 U306.6 ; U305.6 20.36,77.82 v1(20.53,77.99)
  BOTTOM w0.394: C214.1 40.89,11.6 v1(40.4,12.08) ; C148.2 7.62,129.52 v1(6.89,130.24) ; R314.1 v3(38.12,41.9) ; R308.1 35.12,51.49 v3(34.96,51.65) ; U205.2 44.14,11.99 v1(44.23,12.08) ; v1(38.94,12.07) 38.63,11.77 FL203.3 ; J302.4 33.43,83.27 ; J302.4 30.89,83.27 ; J302.4 32.16,82 ; J302.4 32.16,84.54 ; 50.87,70.03 v1(50.87,70.04) ; 50.87,70.03 51.41,69.49 C638.2 ; 50.87,70.03 50.87,70 50.3,69.43 C559.2 ; C156.1 45.52,127.5 v1(45.32,127.7) ; 73.43,48.19 P201.26 ; P201.26 72.35,49.27 ; P201.26 74.51,49.27 ; v1(20.71,17.09) T202.5 v1(19.31,18.49) T202.2 18.67,19.11 v1(18.02,19.77) ; v1(9.13,15.26) 9.56,15.68 C247.1 ; v1(18.74,133.54) 18.86,133.42 C146.1 ; v1(23.78,33.16) 24.16,33.54 24.16,34.03 C266.1 ; v1(37.39,124.88) 37.39,124.44 T107.2 35.19,122.24 ; R225.2 20.17,28.39 v2(20.17,28.36) ; J302.5 37.02,79.68 ; J302.5 35.75,80.95 ; J302.5 35.75,78.41 ; J302.5 34.48,79.68 ; R320.2 v1(19.11,58.1) ; C114.1 13.01,96.74 v1(13.41,97.14) ; v1(33.06,15.46) 33.43,15.83 34.62,15.83 T208.1 ; T105.1 v1(9.43,107.02) ; v3(16.19,36) 16.19,37.79 T207.1 ; v3(16.19,36) T207.2 14.22,37.97 13.78,37.97 v1(13.73,38.02) ; v3(16.19,36) T207.5 ; C256.1 11.4,44.29 v1(11.18,44.51) ; v1(18.02,19.77) 18.02,19.78 19.32,21.09 ; v1(18.02,19.77) 17.34,20.45 T201.5 v1(16.71,21.09) T201.2 v1(15.32,22.48) ; v1(46.35,74.32) 46.63,74.32 47.29,73.66 C611.2 ; 35.75,85.59 J302.3 ; J302.3 35.75,88.13 ; J302.3 37.02,86.86 ; J302.3 34.48,86.86 ; v1(47.91,127.7) 48.03,127.7 48.77,126.96 ; C639.2 54.47,71.42 C640.2 55.68,71.42 C641.2 56.14,71.54 v1(56.83,72.22) ; T106.1 34.35,128.34 v1(34.35,128.36) ; v1(5.48,120.26) 5.59,120.15 C151.1 ; v1(15.63,49.72) 15.7,49.72 16.24,49.19 U204.4 ; C215.1 47.41,11.48 v1(46.81,12.08) ; v1(32.62,55.77) 33.01,56.16 DS301.C ; C147.1 v1(11.83,129.17) ; 72.09,119.23 P101.26 ; P101.26 73.17,118.15 ; P101.26 74.25,119.23 ; P101.26 73.17,120.31 ; v1(49.2,127.7) 48.77,127.27 48.77,126.96 ; C246.1 5.59,16.71 v1(5.48,16.82) ; C619.2 55.13,74.36 v1(55.61,74.84) ; U204.4 20.29,47.56 v1(20.3,47.56) ; U204.4 16.24,47.15 v1(17.56,45.83) ; C153.1 53.14,122.2 v1(52.65,122.69) 53.13,123.17 C154.1 ; C149.1 9.26,119.12 v1(9.17,119.03) ; v1(33.24,110.58) 32.78,111.04 C166.1 ; FL202.1 19.79,42.04 v1(19.79,42.03) ; v1(21.67,123.11) v1(20.27,121.71) v1(18.98,120.42) ; v1(10.33,106.12) v1(12.41,108.21) T105.5 ; U105.4 v1(6.26,93.47) ; U105.4 v1(8.35,91.88) ; U105.4 U105.2 13.27,93.47 v1(13.41,93.32) ; U105.4 v1(8.35,95.1) ; v1(18.74,5.5) 18.86,5.62 C251.1 ; v1(47.42,69.32) 47.25,69.48 C615.2 ; T106.5 v1(30.74,126.53) T106.2 32.62,128.41 v1(32.62,128.87) ; v1(10.83,34.41) T205.1 ; T107.1 36.98,122.24 35.19,122.24 ; v3(39.38,51.68) 39.09,51.39 R306.1 ; C112.1 v1(9.85,89.41) ; v1(9.56,12.18) 10.27,11.47 C248.2 ; T108.1 v1(15.27,104.07) ; 20.02,119.37 18.98,120.41 v1(18.98,120.42) ; C249.1 20.42,10.52 v1(20.77,10.17) ; v1(13.41,90.78) 12.82,90.19 C115.1 ; C254.1 14.74,51.56 v1(14.74,51.56) ; 35.19,122.24 T107.5 ; C150.2 10.5,115.48 v1(9.72,116.26) ; v1(18.98,120.42) T102.2 v1(17.68,119.12) T102.5 16.28,117.72 ; v1(65.31,72.63) 65.29,72.66 63.71,72.66 63.43,72.38 C518.2 62.28,72.38 61.33,72.38 ; v1(25.06,10.17) 24.72,10.52 C250.2 ; T208.5 33.91,18.29 34.51,17.7 34.51,16.91 v1(34.44,16.85) 35.39,16.85 T208.2 ; J302.2 39.34,84.54 ; J302.2 40.61,83.27 ; J302.2 39.34,82 ; J302.2 38.07,83.27 ; C610.2 47.64,74.33 v1(47.6,74.37) ; 48.77,126.96 U104.2 U104.4 ; v1(47.25,67.78) 47.71,68.24 C557.2 48.19,68.24 C558.2 ; v1(54.74,76.24) 53.93,75.43 C618.2 ; R307.1 37.03,51.34 37.42,51.73 v3(37.57,51.73) ; C252.2 15.71,52.17 v1(16.22,51.66) 16.67,52.11 C253.1 ; R328.1 v3(39.89,41.9) ; T108.5 T108.2 14.54,101.55 v1(14.54,101.1) ; C512.2 59.2,69.29 v1(59.34,69.43) 59.7,69.07 C513.2 60.84,69.07 60.86,69.09 C522.2 61.59,69.09 62.05,69.55 C523.2 ; C152.2 v1(52.86,124.14) ; v1(31.48,10.2) 31.48,10.18 T206.1 ; FL203.1 37.87,9.16 v1(36.08,9.16) ; FL202.3 12.25,42.04 v1(11.18,43.1) ; v1(7.92,89.38) C103.2 C113.1 ; v1(11.18,50.11) 11.9,50.83 C255.1 ; v1(9.93,33.52) T205.2 T205.5 ; 76.84,66.73 P501.2 76.03,66.99 ; C614.2 49.37,69.68 v1(49.51,69.53) ; v1(25.94,62.19) 25.32,61.57 C343.2 ; C511.2 v1(57.06,69.23) ; R313.1 v3(35.71,41.9) ; C213.1 C203.2 C212.1 48.43,7.1 v1(48.19,7.34) ; T206.5 v1(30.3,13.16) T206.2 32.37,11.08 v1(32.37,11.09) ; C155.1 52.05,127.43 v1(51.78,127.7) ; R312.1 v3(33.59,41.9) ; C340.2 v1(14.83,79.05) ; R329.1 v3(41.05,41.9) ; C510.2 v1(58.13,69.91) ; C519.2 60.26,72.28
  vias: v1(1.27,122.18) v1(1.27,120.26) v1(1.27,86.62) v1(1.27,84.7) v1(1.27,54.3) v1(1.27,52.38) v1(1.27,18.74) v1(1.27,16.82) v1(2.57,36.52) v1(2.57,34.6) v1(2.67,120.26) v1(2.68,104.4) v1(2.68,102.48) v1(2.69,86.62) v1(2.69,84.7) v1(2.63,54.3) v1(2.6,52.38) v1(2.67,16.82) v1(2.82,122.18) v1(2.82,18.74) v1(3.88,36.52) v1(3.88,34.6) v1(3.98,54.3) v1(3.93,52.38) v1(4.08,120.26) v1(4.08,16.82) v1(4.09,104.4) v1(4.09,102.48) v1(4.1,86.62) v1(4.1,84.7) v1(4.38,122.18) v1(4.38,18.74) v1(4.51,133.14) v1(4.67,5.99) v1(5.18,36.52) v1(5.18,34.6) v1(5.27,52.38) v1(5.34,54.3) v1(5.51,104.4) v1(5.51,102.48) v1(5.52,86.62) v1(5.52,84.7) v1(5.86,134.49) v1(5.87,131.77) v1(5.93,122.18) v1(5.93,18.74) v1(5.9,4.51) v1(6.06,34.24) v1(6.24,7.57) v1(6.6,52.38) v1(6.69,54.3) v1(6.92,104.4) v1(6.92,102.48) v1(6.93,86.62) v1(6.93,84.7) v1(6.96,8.64) v1(7.23,133.13) v1(7.25,126.57) v1(7.25,123.96) v1(7.25,119.03) v1(7.21,33.09) v1(7.21,21.6) v1(7.21,15.26) v1(7.2,13.78) v1(7.22,12.13) v1(7.22,9.91) v1(7.35,117.73) v1(7.29,22.95) v1(7.42,35.59) v1(7.52,24.29) v1(7.63,116.45) v1(7.6,6.21) v1(7.93,52.38) v1(7.89,25.59) v1(8.05,132.12) v1(8.08,115.23) v1(8.05,54.3) v1(8.25,104.57) v1(8.29,102.62) v1(8.35,86.62) v1(8.35,84.7) v1(8.36,31.94) v1(8.41,26.85) v1(8.43,7.3) v1(8.57,34.44) v1(8.67,130.97) v1(8.71,114.08) v1(8.95,8.56) v1(9.04,129.73) v1(9.17,126.95) v1(9.17,125.47) v1(9.12,28.13) v1(9.13,21.6) v1(9.15,13.83) v1(9.13,9.91) v1(9.26,52.38) v1(9.26,51.52) v1(9.26,50.11) v1(9.26,48.71) v1(9.26,47.31) v1(9.26,45.91) v1(9.26,44.51) v1(9.26,43.1) v1(9.26,41.7) v1(9.22,22.93) v1(9.3,123.99) v1(9.3,122.77) v1(9.31,117.62) v1(9.3,20.55) v1(9.3,19.33) v1(9.49,105.09) v1(9.4,54.3) v1(9.48,24.23) v1(9.49,113.03) v1(9.62,103.02) v1(9.76,123.38) v1(9.76,86.62) v1(9.76,84.7) v1(9.76,19.94) v1(9.86,29.14) v1(9.91,25.49) v1(10.22,123.96) v1(10.22,122.77) v1(10.22,20.53) v1(10.22,19.33) v1(10.42,112.11) v1(10.5,26.69) v1(10.66,53.78) v1(10.7,126.91) v1(10.76,30.16) v1(10.84,103.67) v1(11.18,86.62) v1(11.18,84.7) v1(11.18,48.71) v1(11.18,47.31) v1(11.18,45.91) v1(11.24,27.8) v1(11.29,113.91) v1(11.46,111.33) v1(11.91,104.55) v1(12.02,126.89) v1(12.07,119.62) v1(12.07,117.69) v1(12.05,13.61) v1(12.08,11.37) v1(12.1,121.27) v1(12.1,116.24) v1(12.39,113.01) v1(12.59,86.62) v1(12.59,84.7) v1(13.4,98.39) v1(13.41,95.87) v1(13.41,94.6) v1(13.41,92.05) v1(13.41,87.43) v1(13.58,32.68) v1(13.98,112.22) v1(13.96,85.07) v1(14.37,70.38) v1(14.37,68.6) v1(14.86,33.09) v1(14.96,86.07) v1(15.02,10.24) v1(14.99,9.32) v1(15.26,69.49) v1(15.33,98.41) v1(15.33,97.14) v1(15.33,95.87) v1(15.33,94.6) v1(15.33,93.32) v1(15.33,92.05) v1(15.33,90.78) v1(15.33,88.9) v1(15.33,87.43) v1(15.48,129.68) v1(15.48,128.77) v1(15.54,31.23) v1(15.6,9.78) v1(15.91,99.81) v1(16.09,129.22) v1(16.14,70.38) v1(16.14,68.6) v1(16.21,10.24) v1(16.21,9.32) v1(16.42,109.87) v1(16.67,128.77) v1(16.7,129.68) v1(16.82,137.73) v1(16.82,136.17) v1(16.82,134.61) v1(16.82,133.05) v1(16.82,12.1) v1(16.82,5.95) v1(16.82,4.39) v1(16.82,2.83) v1(16.82,1.27) v1(18.65,12.09) v1(18.74,137.73) v1(18.74,136.33) v1(18.74,134.94) v1(18.74,4.09) v1(18.74,2.68) v1(18.74,1.27) v1(20.73,12.12) v1(22.83,10.17) v1(23.7,72.15) v1(23.7,70.68) v1(23.7,69.15) v1(25.2,72.15) v1(25.2,69.15) v1(26.7,72.15) v1(26.7,70.7) v1(26.7,69.15) v1(30.02,17.96) v1(30.89,122.35) v1(30.98,17.06) v1(31.13,130.07) v1(31.12,96.86) v1(31.33,19.14) v1(31.66,87.24) v1(31.91,123.36) v1(31.99,16.23) v1(32.16,120.89) v1(32.28,131.22) v1(32.42,98.16) v1(32.99,13.62) v1(33.13,124.32) v1(33.42,132.37) v1(33.4,10.22) v1(33.63,129.86) v1(33.91,12.69) v1(33.99,9.11) v1(34.18,14.77) v1(34.27,70.73) v1(34.25,69.51) v1(34.3,133.67) v1(34.47,7.51) v1(34.6,137.73) v1(34.6,135.21) v1(34.6,6.06) v1(34.6,4.46) v1(34.6,2.87) v1(34.78,131.01) v1(34.88,70.13) v1(34.82,11.56) v1(35.07,125.27) v1(35.49,70.75) v1(35.49,69.51) v1(35.55,10.29) v1(35.72,132.24) v1(35.92,48.53) v1(35.92,46.49) v1(36.04,126.24) v1(36.32,133.67) v1(36.41,7.51) v1(36.52,137.73) v1(36.52,135.21) v1(36.54,13.61) v1(36.52,6.06) v1(36.52,4.46) v1(36.52,2.87) v1(36.94,47.51) v1(36.91,46.49) v1(37,127.21) v1(36.99,100.06) v1(36.99,97.14) v1(37.74,17.66) v1(37.97,128.17) v1(37.96,48.53) v1(37.98,47.51) v1(37.98,46.49) v1(38.01,57.01) v1(38.55,16.3) v1(38.99,128.96) v1(39.08,14.75) v1(39.33,126.82) v1(39.53,97.14) v1(39.53,57.01) v1(39.53,18.4) v1(39.91,111.37) v1(40.09,129.43) v1(40.17,104.76) v1(40.17,100.19) v1(40.5,127.54) v1(40.94,14.31) v1(41.05,108.95) v1(41.31,98.41) v1(41.44,35.42) v1(41.56,129.63) v1(42.07,25.01) v1(42.54,12.11) v1(42.74,129.61) v1(42.94,14.04) v1(43.21,89.27) v1(43.72,98.29) v1(43.85,95.49) v1(43.85,21.83) v1(44.03,129.61) v1(44.23,13.99) v1(44.36,100.57) v1(44.48,35.29) v1(45.32,129.61) v1(45.5,22.72) v1(45.52,13.99) v1(45.52,12.08) v1(45.63,113.27) v1(46.61,129.61) v1(46.61,127.7) v1(46.77,111.37) v1(46.81,13.99) v1(47.02,98.41) v1(47.28,95.36) v1(47.28,89.4) v1(47.4,100.57) v1(47.91,129.61) v1(47.96,12.05) v1(48.1,13.99) v1(48.42,35.29) v1(48.93,31.86) v1(49.18,26.78) v1(49.2,129.61) v1(49.4,13.99) v1(49.46,12.08) v1(49.82,17.77) v1(49.94,110.6) v1(50.49,129.61) v1(50.49,127.7) v1(50.58,31.86) v1(50.5,13.99) v1(50.69,12.08) v1(50.71,89.27) v1(50.96,100.57) v1(51.09,35.17) v1(51.25,81.61) v1(51.25,80.03) v1(51.24,74.79) v1(51.24,73.21) v1(51.28,68) v1(51.28,66.43) v1(51.26,61.2) v1(51.26,59.73) v1(51.34,21.96) v1(51.78,129.61) v1(51.83,11.53) v1(51.98,13.99) v1(52.03,80.82) v1(52.02,74) v1(52.05,60.41) v1(52.38,137.73) v1(52.38,136.43) v1(52.38,135.14) v1(52.38,133.84) v1(52.38,132.54) v1(52.38,131.25) v1(52.38,10.2) v1(52.38,8.92) v1(52.38,7.65) v1(52.38,6.37) v1(52.38,5.1) v1(52.38,3.82) v1(52.38,2.55) v1(52.38,1.27) v1(52.82,81.61) v1(52.82,80.03) v1(52.81,74.79) v1(52.81,73.21) v1(52.85,68) v1(52.85,66.43) v1(52.84,61.2) v1(52.84,59.73) v1(52.99,29.45) v1(52.99,27.42) v1(53.25,97.52) v1(53.27,13.99) v1(54.14,100.83) v1(54.26,23.1) v1(54.3,137.73) v1(54.3,136.43) v1(54.3,135.14) v1(54.3,133.84) v1(54.3,132.54) v1(54.3,131.25) v1(54.36,129.61) v1(54.36,127.7) v1(54.3,10.2) v1(54.3,8.92) v1(54.3,7.65) v1(54.3,6.37) v1(54.3,5.1) v1(54.3,3.82) v1(54.3,2.55) v1(54.3,1.27) v1(54.56,13.99) v1(54.56,12.08) v1(55.41,20.82) v1(55.41,19.29) v1(55.53,29.45) v1(55.65,129.61) v1(55.65,127.7) v1(55.85,13.99) v1(55.85,12.08) v1(56.17,27.29) v1(56.29,102.73) v1(56.55,37.07) v1(56.94,129.61) v1(56.94,127.7) v1(57.06,30.72) v1(57.14,13.99) v1(57.14,12.08) v1(57.82,23.1) v1(58.23,129.61) v1(58.23,127.7) v1(58.2,102.73) v1(58.2,100.7) v1(58.44,13.99) v1(58.44,12.08) v1(58.83,30.98) v1(58.96,33.52) v1(59.22,113.27) v1(59.52,129.61) v1(59.52,127.7) v1(59.62,62.29) v1(59.72,98.03) v1(59.73,13.99) v1(59.73,12.08) v1(59.86,58.01) v1(59.84,56.71) v1(59.86,55.47) v1(60.1,96.38) v1(60.1,37.07) v1(60.36,19.42) v1(60.49,21.2) v1(60.74,98.92) v1(60.83,58.03) v1(60.8,56.74) v1(60.83,55.44) v1(60.87,23.1) v1(60.99,31.1) v1(60.99,29.58) v1(61.02,13.99) v1(61.02,12.08) v1(61.17,127.69) v1(61.23,129.63) v1(61.74,58.01) v1(61.74,56.74) v1(61.74,55.47) v1(61.88,96.38) v1(62.65,127.7) v1(62.64,27.42) v1(62.64,12.03) v1(62.82,14.01) v1(63.03,100.83) v1(63.79,36.94) v1(64.3,27.29) v1(64.53,129.62) v1(64.54,127.7) v1(64.88,14) v1(64.93,21.2) v1(65.06,19.42) v1(65.29,71.34) v1(65.31,70.09) v1(65.59,83.5) v1(65.59,82.54) v1(66.28,72.66) v1(66.25,71.36) v1(66.28,70.07) v1(66.27,13.92) v1(66.28,11.97) v1(66.43,129.62) v1(66.43,127.7) v1(66.58,83.53) v1(66.58,82.54) v1(66.84,108.32) v1(66.96,34.91) v1(67.09,25.51) v1(67.19,71.36) v1(67.19,70.09) v1(67.47,102.86) v1(67.47,65.62) v1(67.47,64.43) v1(67.57,83.53) v1(67.57,82.54) v1(67.54,11.5) v1(67.61,13.57) v1(67.86,129.9) v1(67.89,127.89) v1(68.23,106.41) v1(68.44,65.04) v1(68.62,10.72) v1(68.87,98.79) v1(68.87,36.82) v1(68.85,12.95) v1(69.07,130.71) v1(69.25,128.45) v1(69.4,65.62) v1(69.4,64.43) v1(69.46,9.68) v1(69.88,131.92) v1(69.88,21.32) v1(69.95,12.1) v1(69.98,8.45) v1(70.01,19.55) v1(70.16,137.73) v1(70.16,136.27) v1(70.16,134.81) v1(70.16,133.35) v1(70.14,31.23) v1(70.16,7.12) v1(70.16,5.66) v1(70.16,4.2) v1(70.16,2.73) v1(70.42,129.35) v1(70.39,25.26) v1(70.77,34.79) v1(70.85,11.05) v1(71.15,108.32) v1(71.15,92.82) v1(71.32,130.52) v1(71.52,9.83) v1(71.89,131.89) v1(71.94,8.51) v1(72.08,137.73) v1(72.08,136.27) v1(72.08,134.81) v1(72.08,133.35) v1(72.08,7.12) v1(72.08,5.66) v1(72.08,4.2) v1(72.08,2.73) v1(72.3,31.48) v1(72.42,26.15) v1(72.42,20.18) v1(72.55,34.91) v1(74.2,29.32) v1(75.22,22.59) v1(75.22,21.07) v1(76.36,106.79) v1(77,119.18) v1(88.62,133.97) v1(89.82,119.88) v1(89.82,114.8) v1(89.82,44.84) v2(17.69,111.62) v2(19.16,111.44) v2(19.85,110.15) v2(21.14,29.38) v3(16,98.32) v3(16,96.3) v3(16,94.28) v3(17.81,100.35) v3(17.81,98.34) v3(17.81,96.33) v3(17.81,94.33) v3(17.85,90.32) v3(19,89.16) v3(19.13,91.6) v3(19.8,98.9) v3(20.16,88) v3(20.29,90.44) v3(20.5,92.97) v3(20.75,102.02) v3(21.32,86.84) v3(21.45,89.29) v3(21.62,91.85) v3(22.48,85.69) v3(22.57,102.02) v3(22.6,88.13) v3(22.74,90.72) v3(23.46,104.19) v3(23.64,84.53) v3(23.76,86.97) v3(23.86,89.6) v3(24.8,83.37) v3(24.98,88.48) v3(24.92,85.81) v3(25.5,103.21) v3(25.95,82.21) v3(26.08,84.65) v3(26.11,87.36) v3(26.84,50.1) v3(26.84,48.46) v3(26.84,45.2) v3(26.83,43.8) v3(27.07,55.78) v3(27.11,81.05) v3(27.23,86.23) v3(27.21,83.54) v3(27.69,58.7) v3(28.03,20.08) v3(28.27,79.89) v3(28.22,59.62) v3(28.35,85.11) v3(28.4,82.34) v3(28.68,48.45) v3(28.68,45.48) v3(28.76,55.89) v3(28.71,50.1) v3(28.71,47.21) v3(29.13,60.76) v3(29.21,21.46) v3(29.47,83.99) v3(29.43,78.74) v3(29.55,81.18) v3(29.8,58.59) v3(30.47,59.36) v3(30.59,77.58) v3(30.59,50.1) v3(30.6,82.87) v3(30.67,62.37) v3(30.59,48.25) v3(30.59,47.05) v3(30.71,80.02) v3(30.79,55.8) v3(30.86,39.2) v3(31.11,41.9) v3(31.72,81.74) v3(31.74,76.42) v3(31.87,78.86) v3(31.8,63.42) v3(32.02,60.93) v3(33.03,77.7) v3(33.01,75.14) v3(33.08,64.7) v3(33.15,62.03) v3(33.34,59.63) v3(33.46,39.21) v3(34.19,76.55) v3(34.2,63.6) v3(34.43,60.75) v3(35.16,33.02) v3(36.16,63.73) v3(36.18,36.03) v3(36.1,26.88) v3(36.7,35.24) v3(37.53,25.5) v3(38.07,30.12) v3(74.79,96.23) v3(74.79,26.28) v3(74.76,24.96) v3(74.81,95.03) v3(77.43,98.66) v3(77.43,28.66) v3(78.07,88) v3(78.07,18.04) v3(78.2,103.68) v3(78.2,33.73) v3(78.46,91.17) v3(78.46,21.22) v3(81.69,35.82) v3(81.82,94.03) v3(81.82,24.07) v3(81.95,32.01) v3(82.56,101.38) v3(82.56,100.06) v3(82.65,122.92) v3(82.65,79.74) v3(82.65,52.97) v3(82.65,31.44) v3(82.65,30.11) v3(82.65,9.79) v3(83.15,93.08) v3(83.15,89.2) v3(83.15,23.12) v3(83.15,19.25) v3(83.47,97.46) v3(83.47,27.5) v3(86.46,95.75) v3(86.46,92.44) v3(86.46,25.79) v3(86.46,22.49) v3(86.52,98.03) v3(86.52,28.08)
